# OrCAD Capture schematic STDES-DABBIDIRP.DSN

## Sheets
1 AUX_SECTION: size B
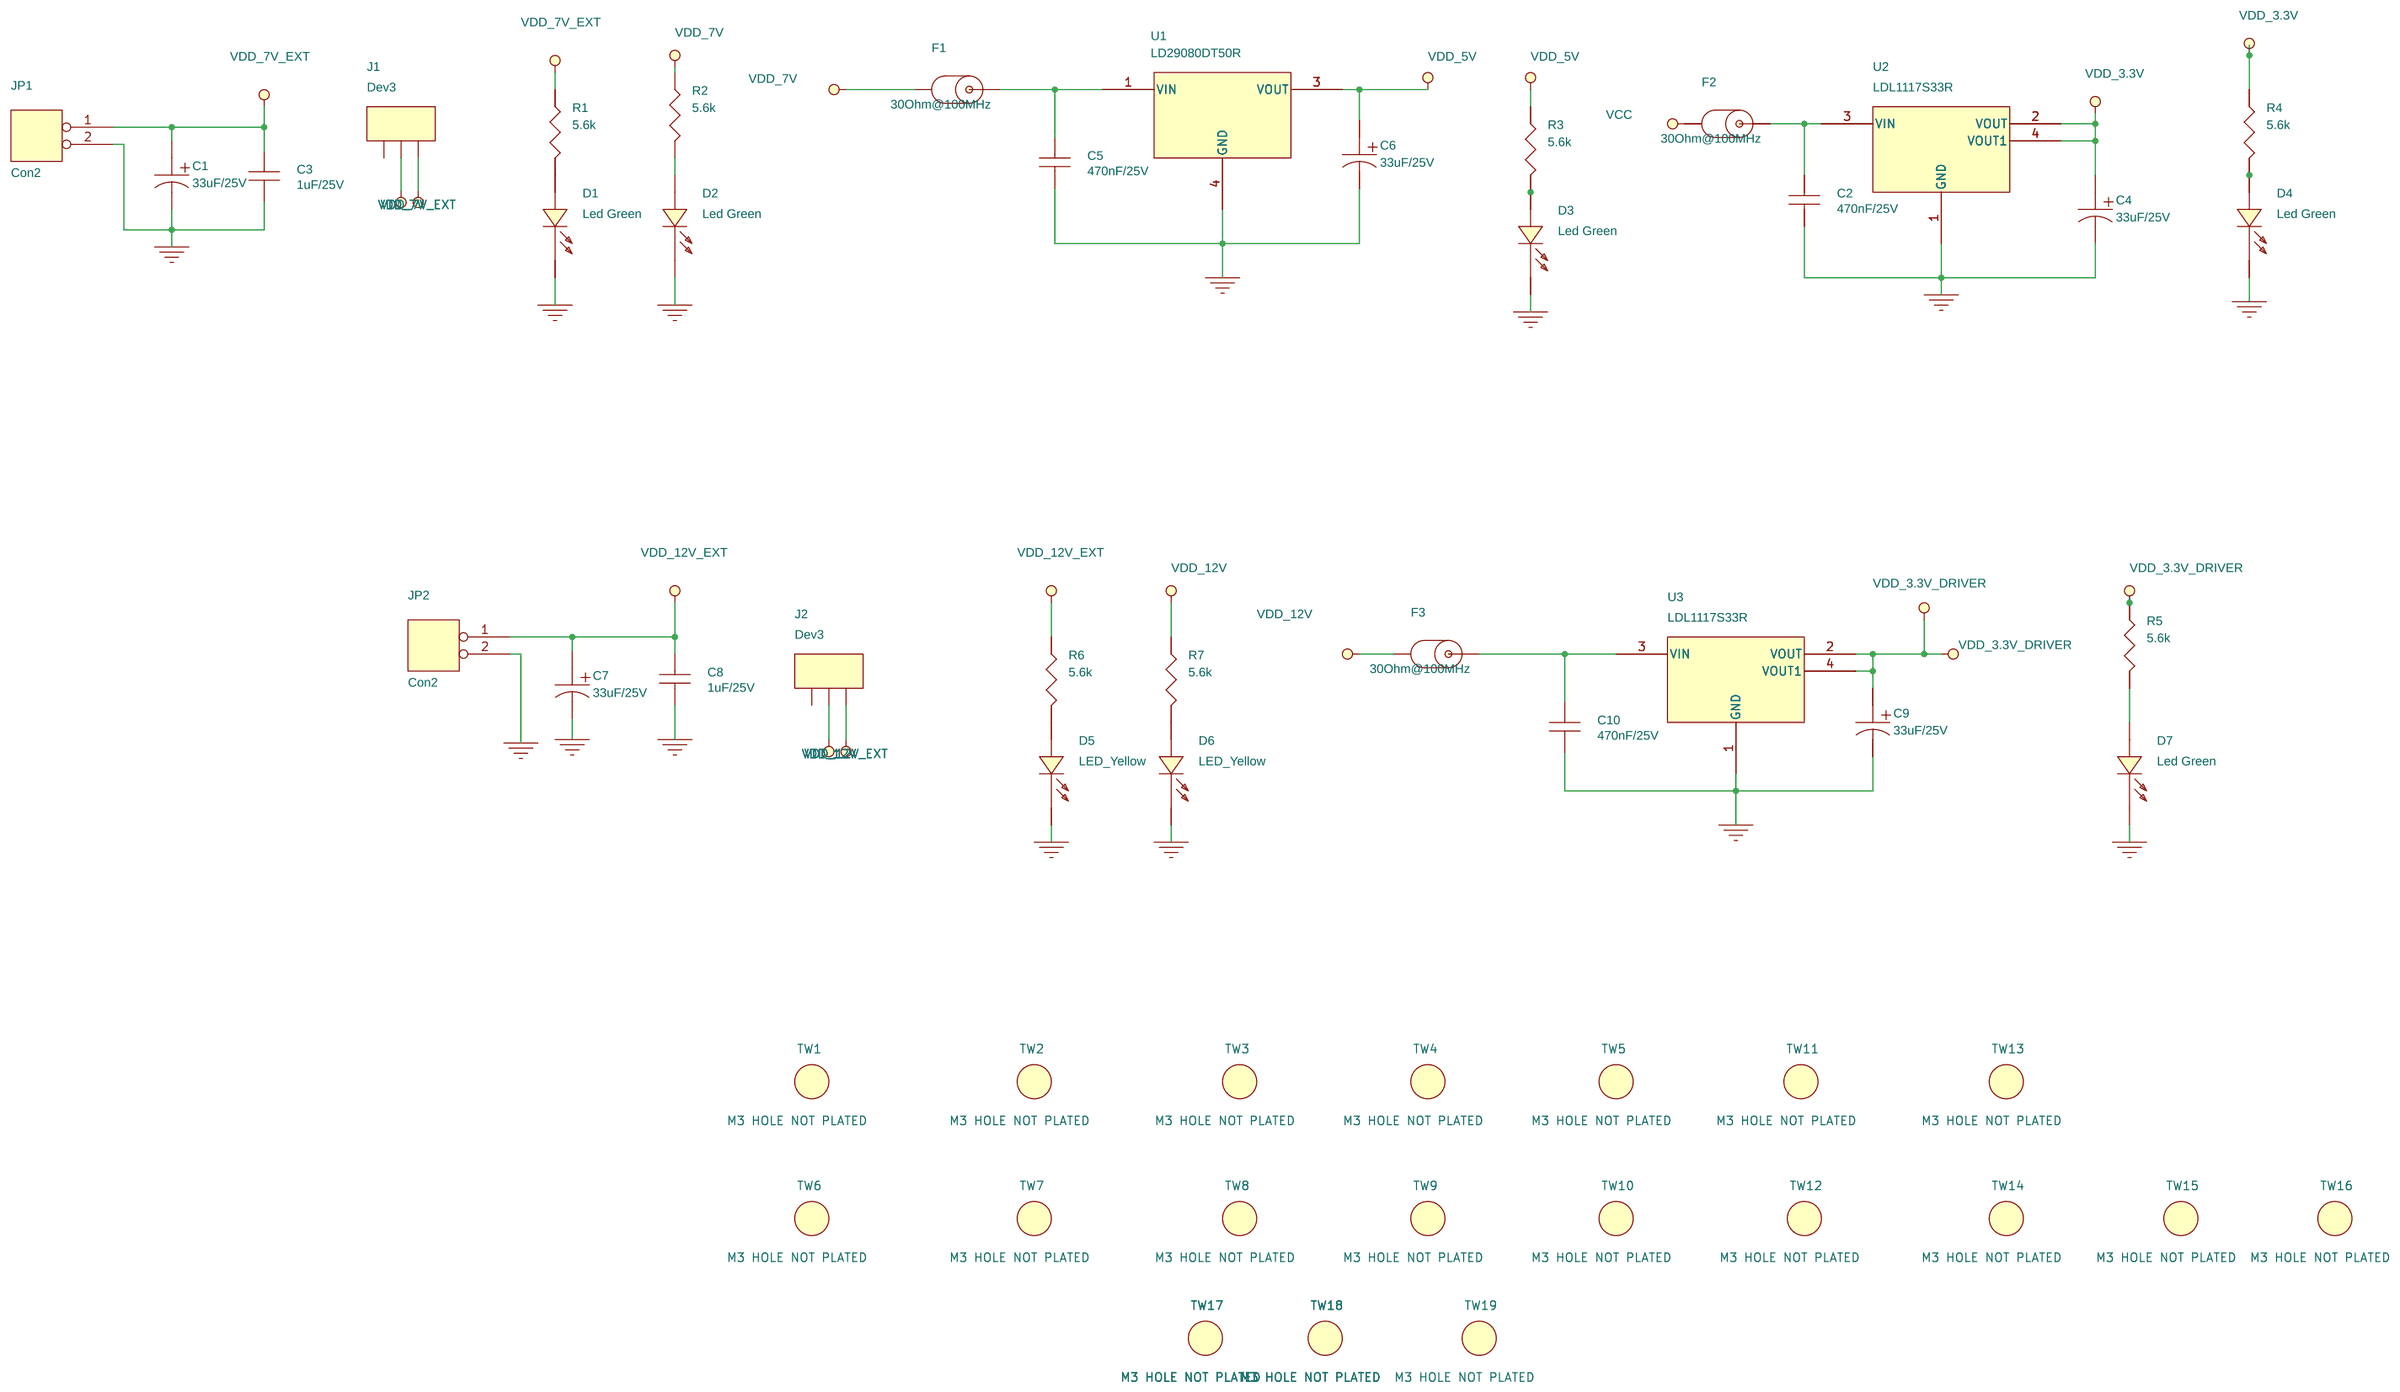
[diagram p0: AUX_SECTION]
2 TEMP_SECTION: size C
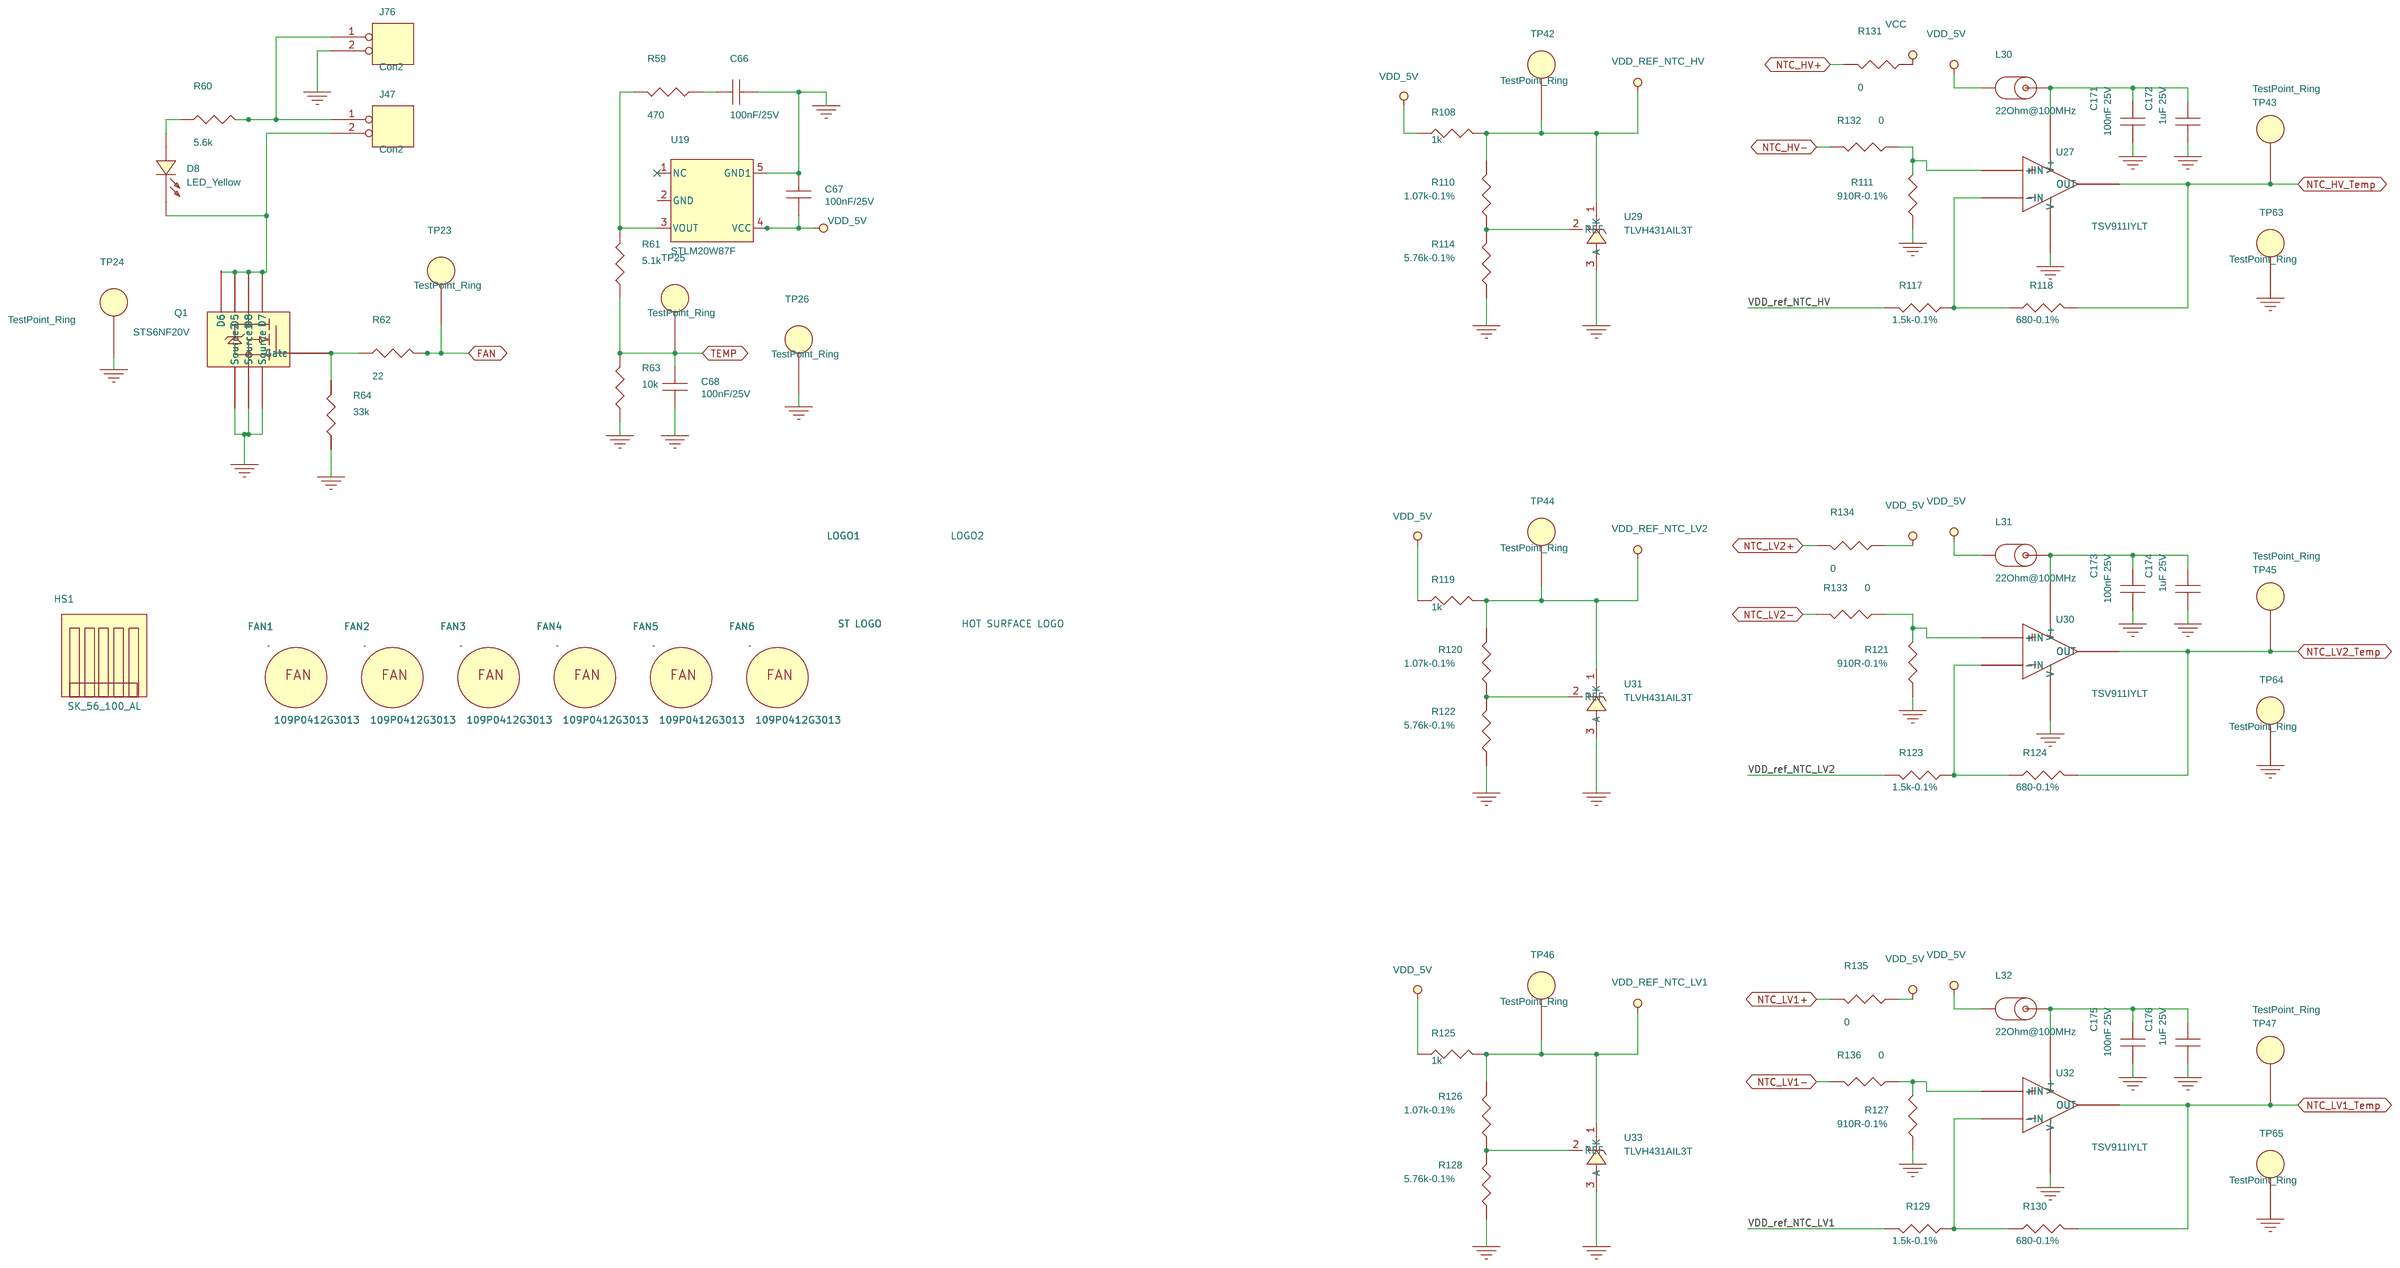
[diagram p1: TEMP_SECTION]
3 SENSE_SECTION: size D
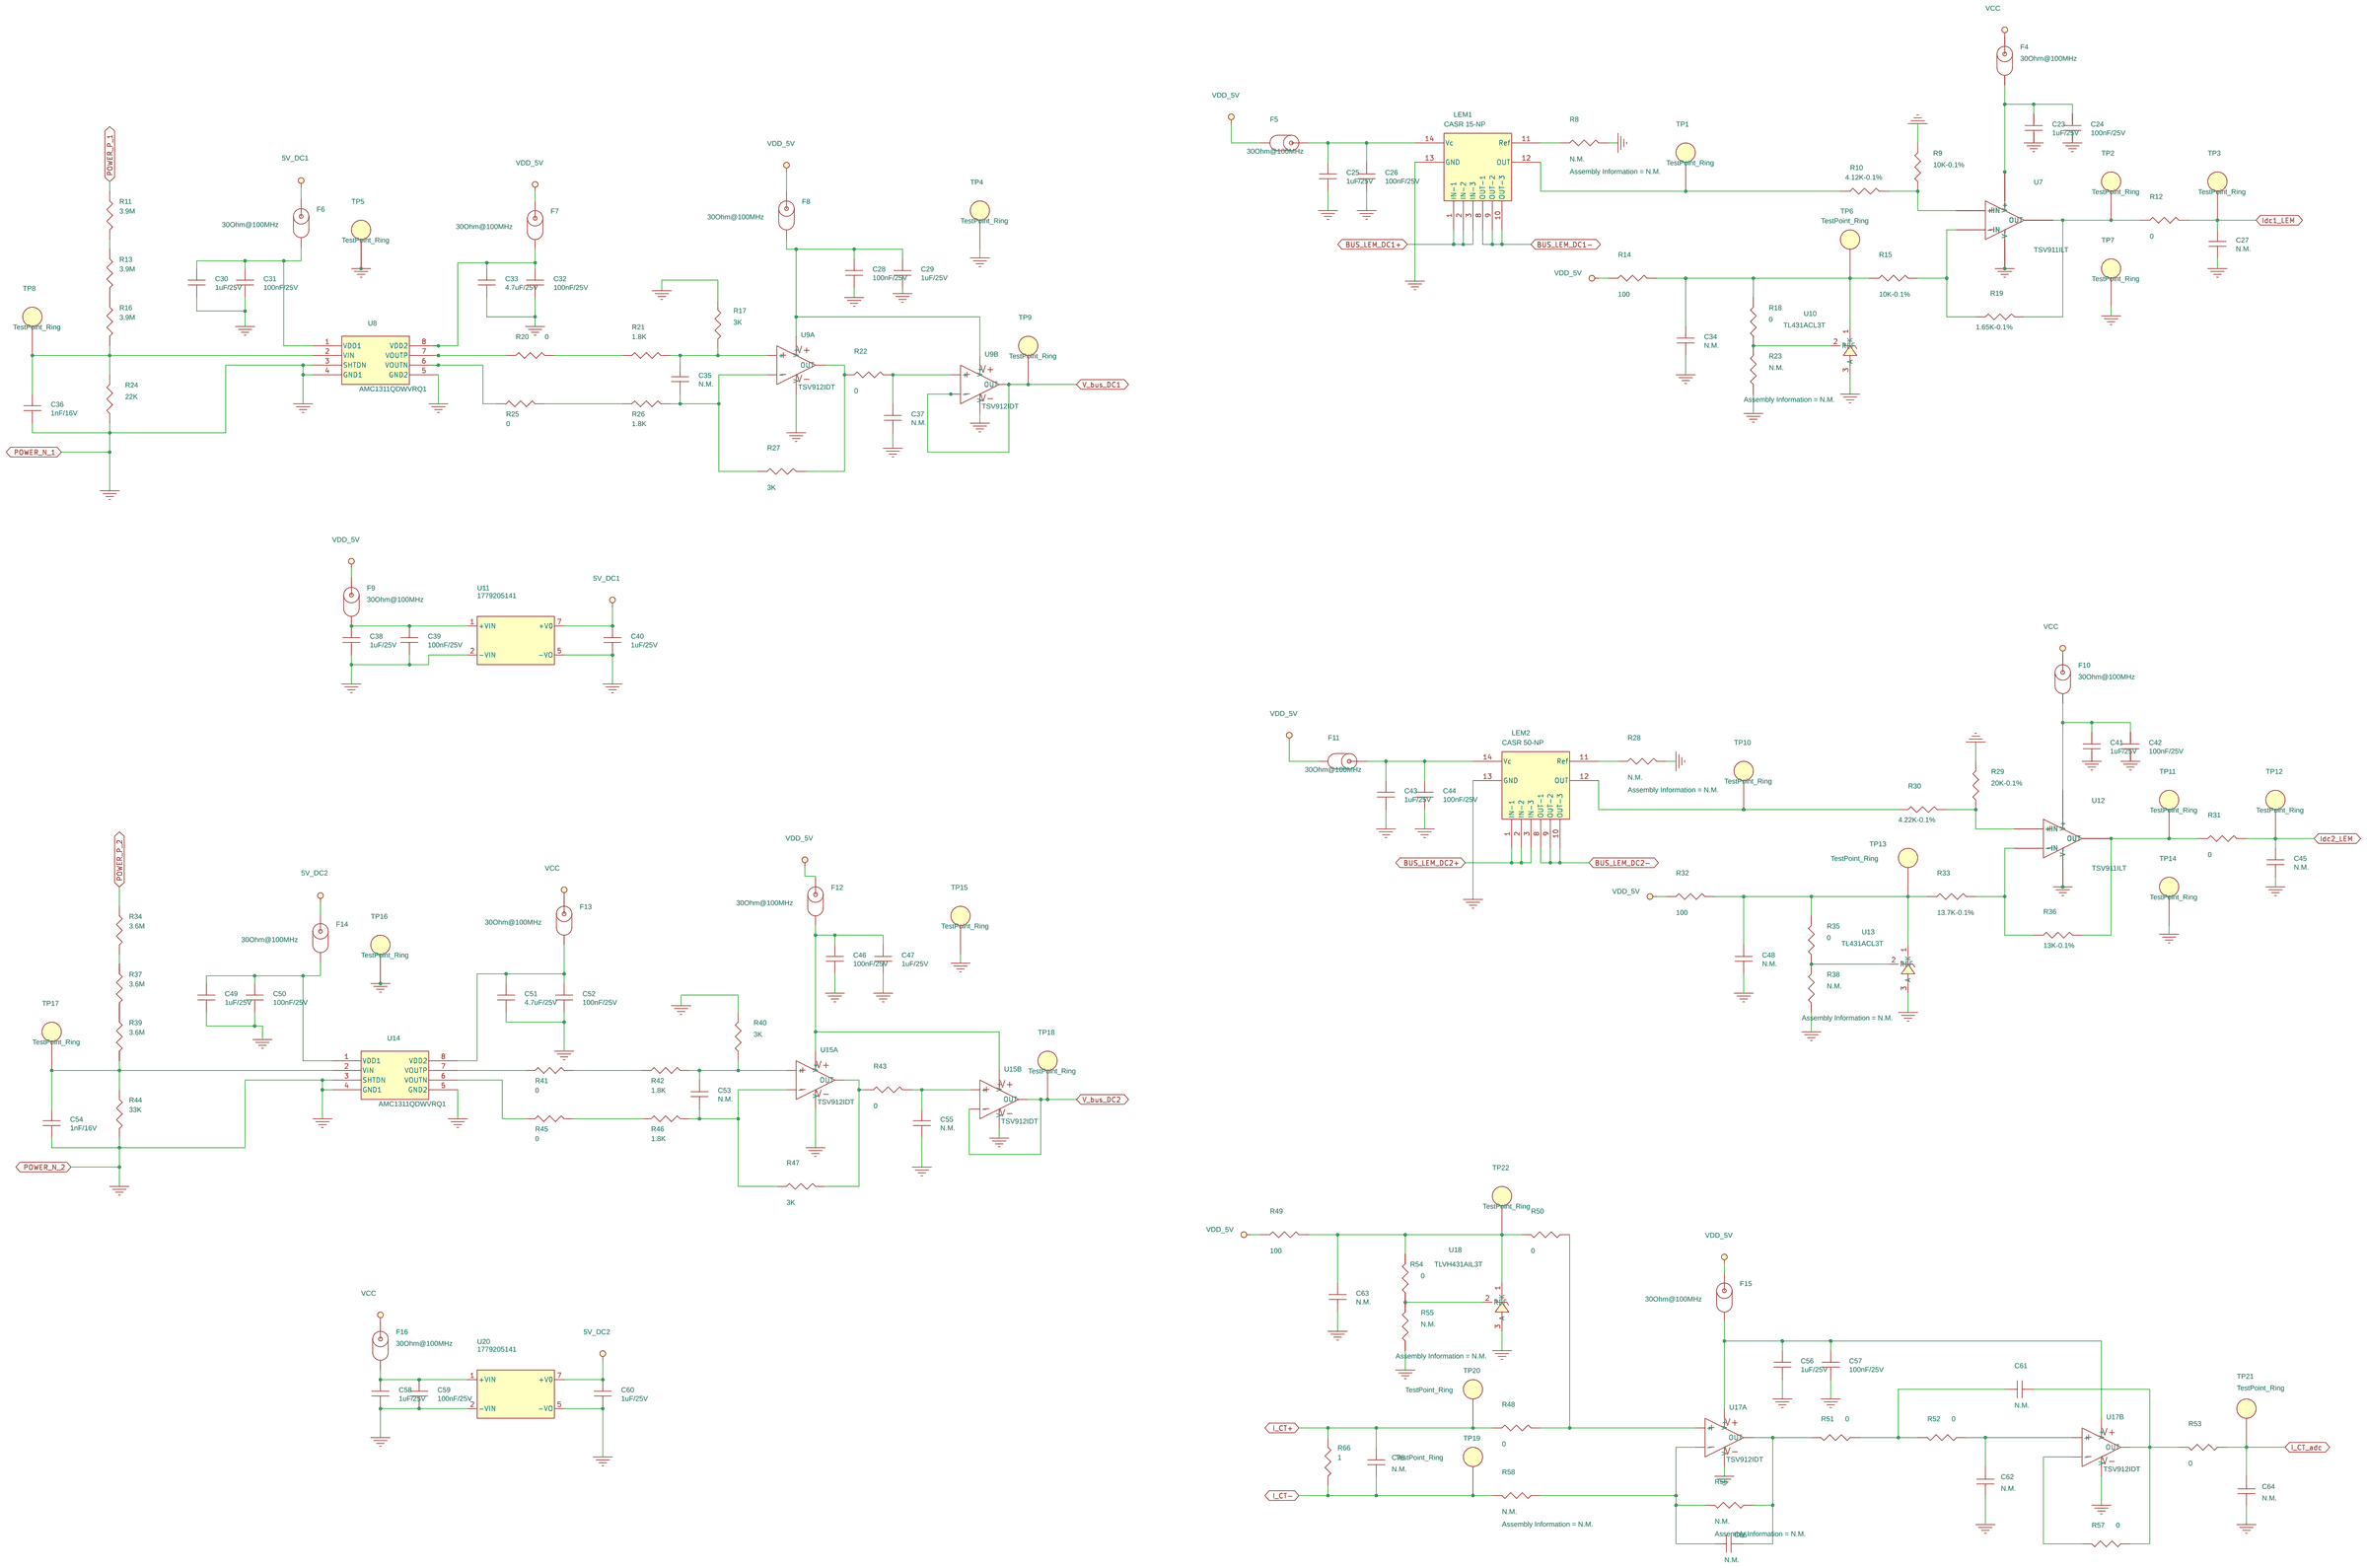
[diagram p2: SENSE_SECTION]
4 CONNECTOR: size B
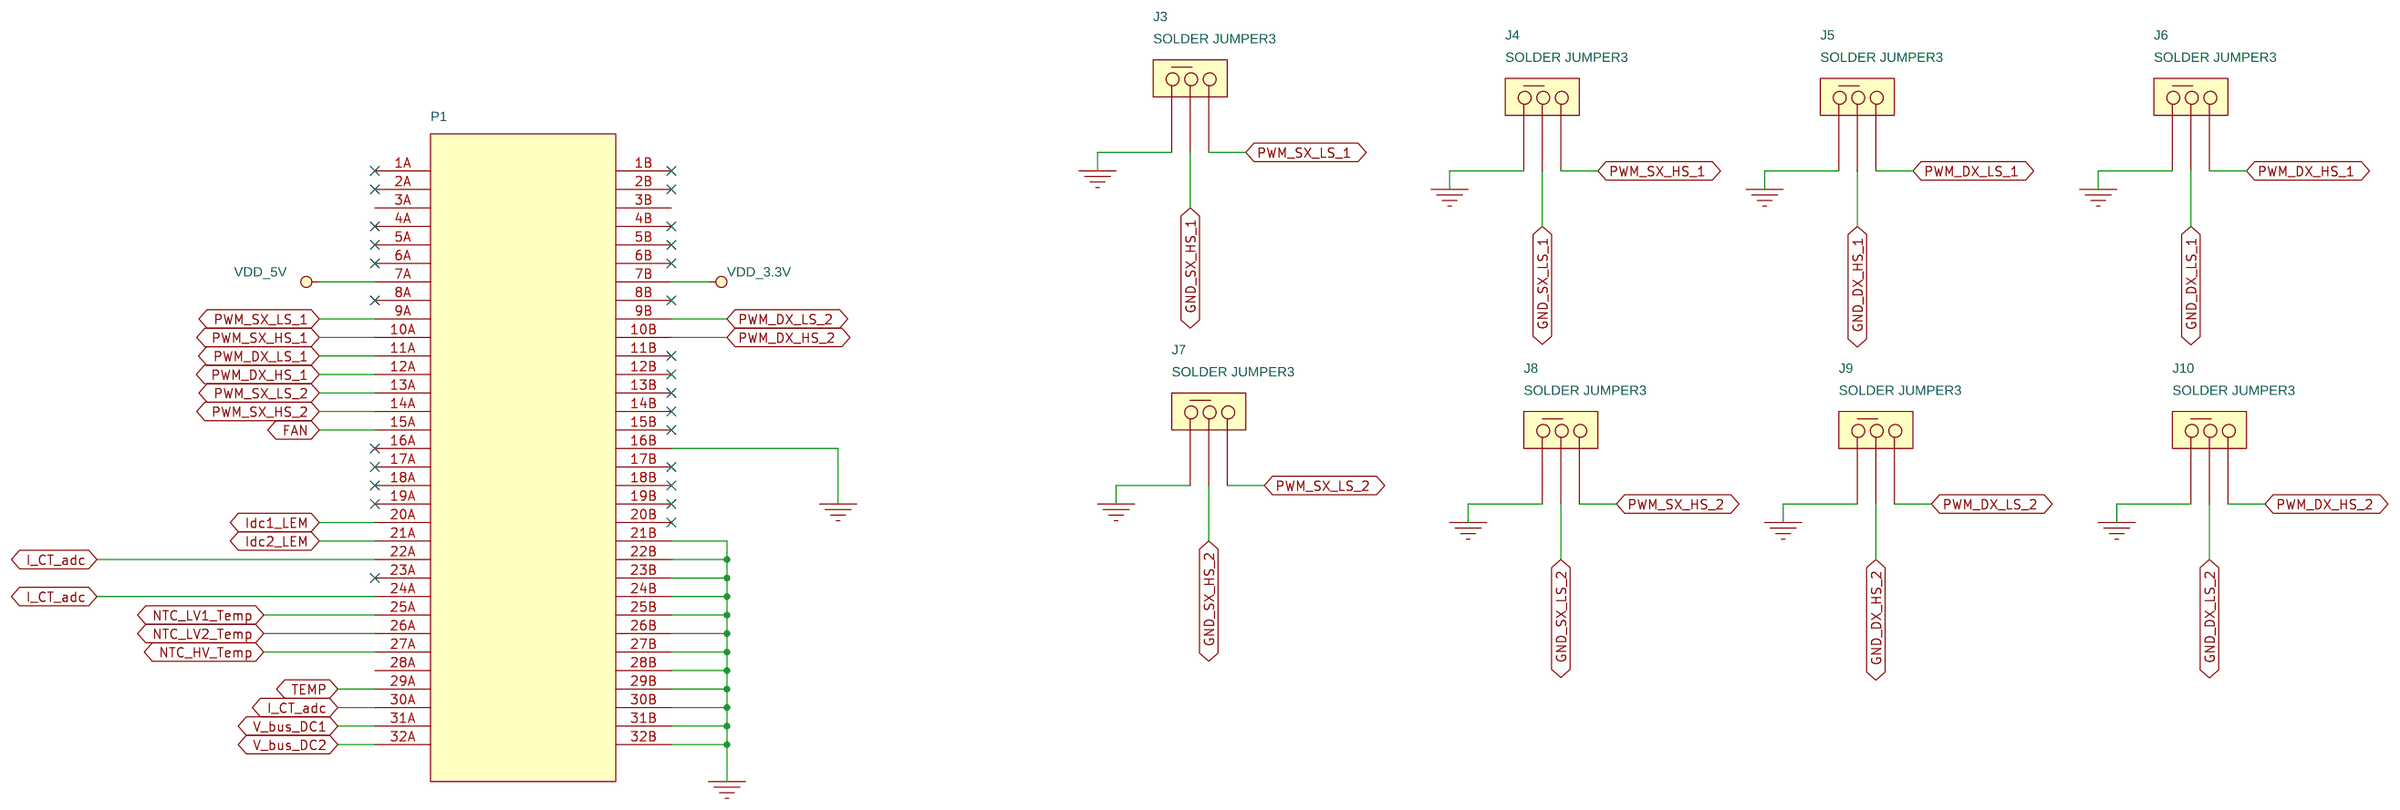
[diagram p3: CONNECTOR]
5 DRIVER_SECTION: size A
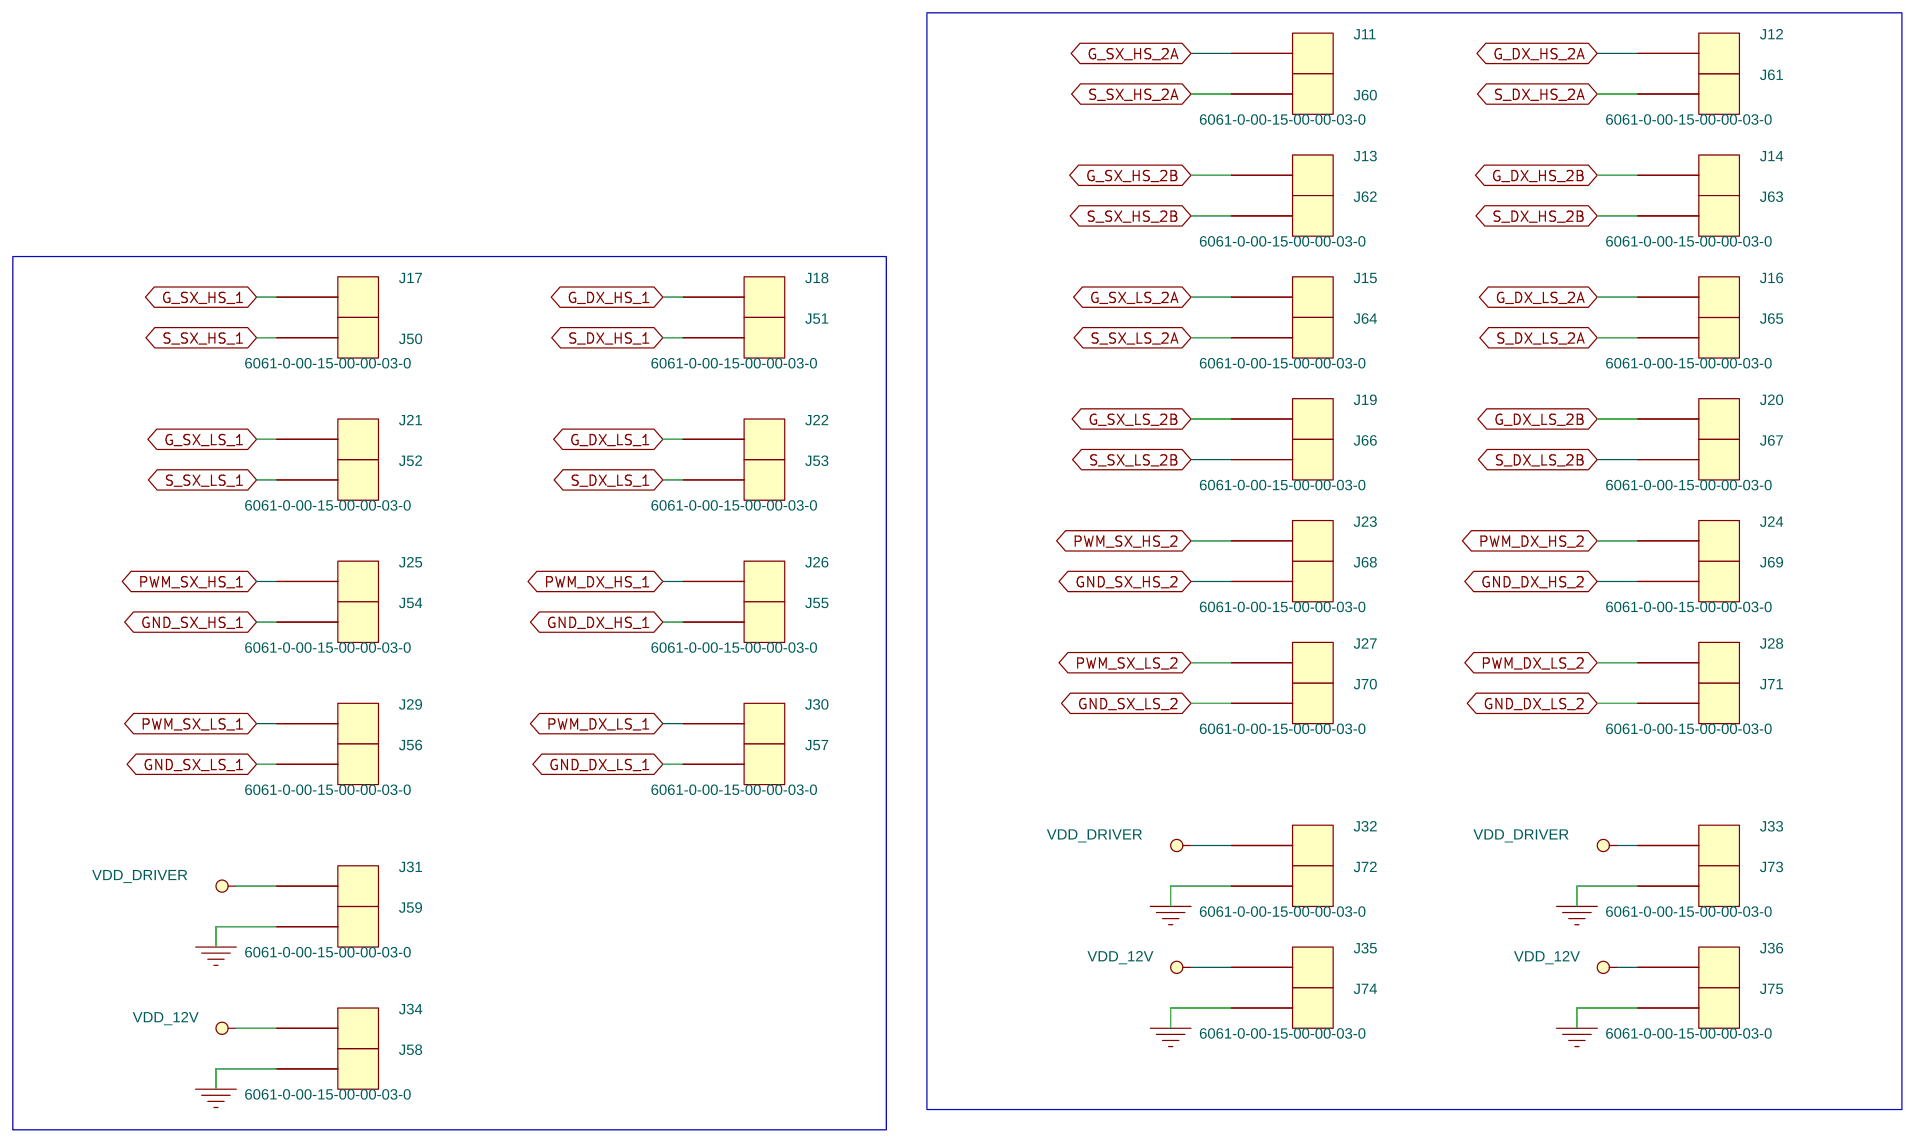
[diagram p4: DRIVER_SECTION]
6 POWER_SECTION: size C
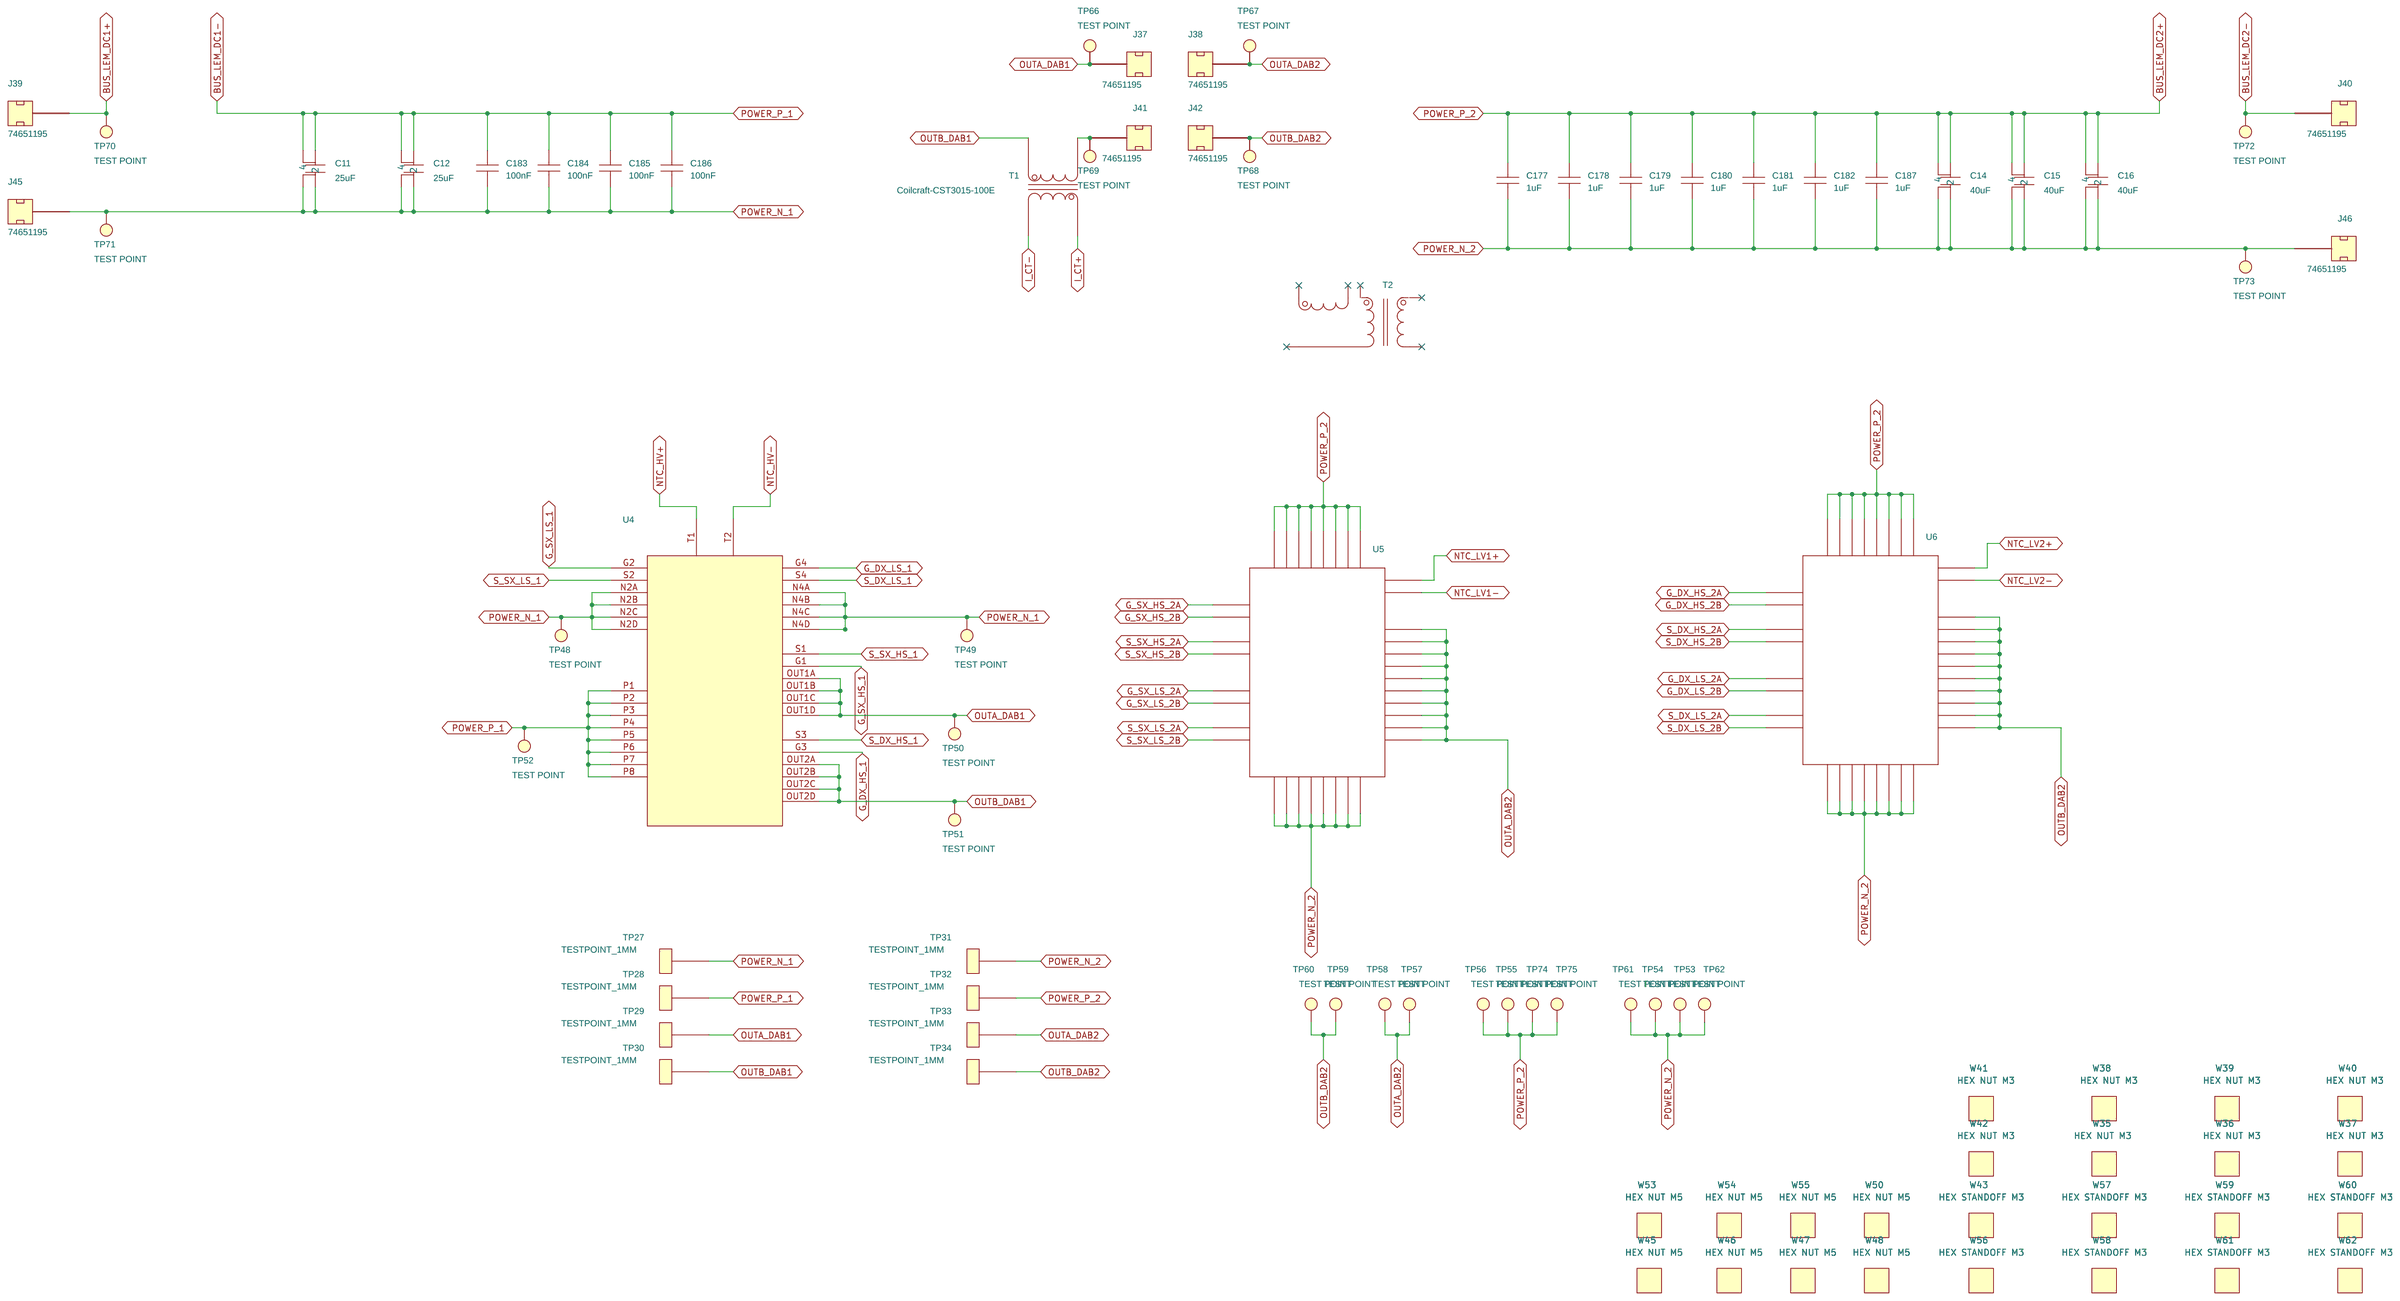
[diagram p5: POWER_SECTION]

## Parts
sheet AUX_SECTION
C1  33uF/25V  [6P6x6P6]
C2  470nF/25V  [C_0603]
C3  1uF/25V  [C_0603]
C4  33uF/25V  [6P6x6P6]
C5  470nF/25V  [C_0603]
C6  33uF/25V  [6P6x6P6]
C7  33uF/25V  [6P6x6P6]
C8  1uF/25V  [C_0603]
C9  33uF/25V  [6P6x6P6]
C10  470nF/25V  [C_0603]
D1  Led Green  [ledc200x125x80l50_55n]
D2  Led Green  [ledc200x125x80l50_55n]
D3  Led Green  [ledc200x125x80l50_55n]
D4  Led Green  [ledc200x125x80l50_55n]
D5  LED_Yellow  [ledc200x125x80l50_55n]
D6  LED_Yellow  [ledc200x125x80l50_55n]
D7  Led Green  [ledc200x125x80l50_55n]
F1  30Ohm@100MHz  [L_0805]
F2  30Ohm@100MHz  [L_0805]
F3  30Ohm@100MHz  [L_0805]
J1  Dev3  [SWITCH_3P]
J2  Dev3  [SWITCH_3P]
JP1  Con2  [Mor2x508]
JP2  Con2  [Mor2x508]
R1  5.6k  [r_1206]
R2  5.6k  [r_1206]
R3  5.6k  [r_1206]
R4  5.6k  [r_1206]
R5  5.6k  [r_1206]
R6  5.6k  [r_1206]
R7  5.6k  [r_1206]
TW1  M3 HOLE NOT PLATED  [vite-m3-noplated]
TW2  M3 HOLE NOT PLATED  [vite-m3-noplated]
TW3  M3 HOLE NOT PLATED  [vite-m3-noplated]
TW4  M3 HOLE NOT PLATED  [vite-m3-noplated]
TW5  M3 HOLE NOT PLATED  [vite-m3-noplated]
TW6  M3 HOLE NOT PLATED  [vite-m3-noplated]
TW7  M3 HOLE NOT PLATED  [vite-m3-noplated]
TW8  M3 HOLE NOT PLATED  [vite-m3-noplated]
TW9  M3 HOLE NOT PLATED  [vite-m3-noplated]
TW10  M3 HOLE NOT PLATED  [vite-m3-noplated]
TW11  M3 HOLE NOT PLATED  [vite-m3-noplated]
TW12  M3 HOLE NOT PLATED  [vite-m3-noplated]
TW13  M3 HOLE NOT PLATED  [vite-m3-noplated]
TW14  M3 HOLE NOT PLATED  [vite-m3-noplated]
TW15  M3 HOLE NOT PLATED  [vite-m3-noplated]
TW16  M3 HOLE NOT PLATED  [vite-m3-noplated]
TW17  M3 HOLE NOT PLATED  [vite-m3-noplated]
TW18  M3 HOLE NOT PLATED  [vite-m3-noplated]
TW19  M3 HOLE NOT PLATED  [vite-m3-noplated]
U1  LD29080DT50R  [dpak4p228_972x240l120x77t520]
U2  LDL1117S33R  [sot223-4p230_700x190l65x72]
U3  LDL1117S33R  [sot223-4p230_700x190l65x72]
sheet CONNECTOR
J3  SOLDER JUMPER3  [jumper_0603_3pin_drop]
J4  SOLDER JUMPER3  [jumper_0603_3pin_drop]
J5  SOLDER JUMPER3  [jumper_0603_3pin_drop]
J6  SOLDER JUMPER3  [jumper_0603_3pin_drop]
J7  SOLDER JUMPER3  [jumper_0603_3pin_drop]
J8  SOLDER JUMPER3  [jumper_0603_3pin_drop]
J9  SOLDER JUMPER3  [jumper_0603_3pin_drop]
J10  SOLDER JUMPER3  [jumper_0603_3pin_drop]
P1  CON64AB  [connERNI_284166_Female32X2]
sheet DRIVER_SECTION
J11  6061-0-00-15-00-00-03-0  [6061-0-00-15-00-00-03-0]
J12  6061-0-00-15-00-00-03-0  [6061-0-00-15-00-00-03-0]
J13  6061-0-00-15-00-00-03-0  [6061-0-00-15-00-00-03-0]
J14  6061-0-00-15-00-00-03-0  [6061-0-00-15-00-00-03-0]
J15  6061-0-00-15-00-00-03-0  [6061-0-00-15-00-00-03-0]
J16  6061-0-00-15-00-00-03-0  [6061-0-00-15-00-00-03-0]
J17  6061-0-00-15-00-00-03-0  [6061-0-00-15-00-00-03-0]
J18  6061-0-00-15-00-00-03-0  [6061-0-00-15-00-00-03-0]
J19  6061-0-00-15-00-00-03-0  [6061-0-00-15-00-00-03-0]
J20  6061-0-00-15-00-00-03-0  [6061-0-00-15-00-00-03-0]
J21  6061-0-00-15-00-00-03-0  [6061-0-00-15-00-00-03-0]
J22  6061-0-00-15-00-00-03-0  [6061-0-00-15-00-00-03-0]
J23  6061-0-00-15-00-00-03-0  [6061-0-00-15-00-00-03-0]
J24  6061-0-00-15-00-00-03-0  [6061-0-00-15-00-00-03-0]
J25  6061-0-00-15-00-00-03-0  [6061-0-00-15-00-00-03-0]
J26  6061-0-00-15-00-00-03-0  [6061-0-00-15-00-00-03-0]
J27  6061-0-00-15-00-00-03-0  [6061-0-00-15-00-00-03-0]
J28  6061-0-00-15-00-00-03-0  [6061-0-00-15-00-00-03-0]
J29  6061-0-00-15-00-00-03-0  [6061-0-00-15-00-00-03-0]
J30  6061-0-00-15-00-00-03-0  [6061-0-00-15-00-00-03-0]
J31  6061-0-00-15-00-00-03-0  [6061-0-00-15-00-00-03-0]
J32  6061-0-00-15-00-00-03-0  [6061-0-00-15-00-00-03-0]
J33  6061-0-00-15-00-00-03-0  [6061-0-00-15-00-00-03-0]
J34  6061-0-00-15-00-00-03-0  [6061-0-00-15-00-00-03-0]
J35  6061-0-00-15-00-00-03-0  [6061-0-00-15-00-00-03-0]
J36  6061-0-00-15-00-00-03-0  [6061-0-00-15-00-00-03-0]
J50  6061-0-00-15-00-00-03-0  [6061-0-00-15-00-00-03-0]
J51  6061-0-00-15-00-00-03-0  [6061-0-00-15-00-00-03-0]
J52  6061-0-00-15-00-00-03-0  [6061-0-00-15-00-00-03-0]
J53  6061-0-00-15-00-00-03-0  [6061-0-00-15-00-00-03-0]
J54  6061-0-00-15-00-00-03-0  [6061-0-00-15-00-00-03-0]
J55  6061-0-00-15-00-00-03-0  [6061-0-00-15-00-00-03-0]
J56  6061-0-00-15-00-00-03-0  [6061-0-00-15-00-00-03-0]
J57  6061-0-00-15-00-00-03-0  [6061-0-00-15-00-00-03-0]
J58  6061-0-00-15-00-00-03-0  [6061-0-00-15-00-00-03-0]
J59  6061-0-00-15-00-00-03-0  [6061-0-00-15-00-00-03-0]
J60  6061-0-00-15-00-00-03-0  [6061-0-00-15-00-00-03-0]
J61  6061-0-00-15-00-00-03-0  [6061-0-00-15-00-00-03-0]
J62  6061-0-00-15-00-00-03-0  [6061-0-00-15-00-00-03-0]
J63  6061-0-00-15-00-00-03-0  [6061-0-00-15-00-00-03-0]
J64  6061-0-00-15-00-00-03-0  [6061-0-00-15-00-00-03-0]
J65  6061-0-00-15-00-00-03-0  [6061-0-00-15-00-00-03-0]
J66  6061-0-00-15-00-00-03-0  [6061-0-00-15-00-00-03-0]
J67  6061-0-00-15-00-00-03-0  [6061-0-00-15-00-00-03-0]
J68  6061-0-00-15-00-00-03-0  [6061-0-00-15-00-00-03-0]
J69  6061-0-00-15-00-00-03-0  [6061-0-00-15-00-00-03-0]
J70  6061-0-00-15-00-00-03-0  [6061-0-00-15-00-00-03-0]
J71  6061-0-00-15-00-00-03-0  [6061-0-00-15-00-00-03-0]
J72  6061-0-00-15-00-00-03-0  [6061-0-00-15-00-00-03-0]
J73  6061-0-00-15-00-00-03-0  [6061-0-00-15-00-00-03-0]
J74  6061-0-00-15-00-00-03-0  [6061-0-00-15-00-00-03-0]
J75  6061-0-00-15-00-00-03-0  [6061-0-00-15-00-00-03-0]
sheet POWER_SECTION
C11  25uF  [WCAP-FTDB_42x45x60_cs]
C12  25uF  [WCAP-FTDB_42x45x60_cs]
C14  40uF  [WCAP-FTDB_42x30x45_cs]
C15  40uF  [WCAP-FTDB_42x30x45_cs]
C16  40uF  [WCAP-FTDB_42x30x45_cs]
C177  1uF  [C_2220]
C178  1uF  [C_2220]
C179  1uF  [C_2220]
C180  1uF  [C_2220]
C181  1uF  [C_2220]
C182  1uF  [C_2220]
C183  100nF  [C_2220]
C184  100nF  [C_2220]
C185  100nF  [C_2220]
C186  100nF  [C_2220]
C187  1uF  [C_2220]
J37  74651195  [wurth_74651195]
J38  74651195  [wurth_74651195]
J39  74651195  [wurth_74651195]
J40  74651195  [wurth_74651195]
J41  74651195  [wurth_74651195]
J42  74651195  [wurth_74651195]
J45  74651195  [wurth_74651195]
J46  74651195  [wurth_74651195]
T1  Coilcraft-CST3015-100E  [transf_Coilcraft-CST3015]
T2  Frenetic_32011-04  [Frenetic_32011-04_temp]
TP27  TESTPOINT_1MM  [TESTPOINT_1MM_SMD]
TP28  TESTPOINT_1MM  [TESTPOINT_1MM_SMD]
TP29  TESTPOINT_1MM  [TESTPOINT_1MM_SMD]
TP30  TESTPOINT_1MM  [TESTPOINT_1MM_SMD]
TP31  TESTPOINT_1MM  [TESTPOINT_1MM_SMD]
TP32  TESTPOINT_1MM  [TESTPOINT_1MM_SMD]
TP33  TESTPOINT_1MM  [TESTPOINT_1MM_SMD]
TP34  TESTPOINT_1MM  [TESTPOINT_1MM_SMD]
TP48  TEST POINT  [harwin_s1751-46r]
TP49  TEST POINT  [harwin_s1751-46r]
TP50  TEST POINT  [harwin_s1751-46r]
TP51  TEST POINT  [harwin_s1751-46r]
TP52  TEST POINT  [harwin_s1751-46r]
TP53  TEST POINT  [harwin_s1751-46r]
TP54  TEST POINT  [harwin_s1751-46r]
TP55  TEST POINT  [harwin_s1751-46r]
TP56  TEST POINT  [harwin_s1751-46r]
TP57  TEST POINT  [harwin_s1751-46r]
TP58  TEST POINT  [harwin_s1751-46r]
TP59  TEST POINT  [harwin_s1751-46r]
TP60  TEST POINT  [harwin_s1751-46r]
TP61  TEST POINT  [harwin_s1751-46r]
TP62  TEST POINT  [harwin_s1751-46r]
TP66  TEST POINT  [harwin_s1751-46r]
TP67  TEST POINT  [harwin_s1751-46r]
TP68  TEST POINT  [harwin_s1751-46r]
TP69  TEST POINT  [harwin_s1751-46r]
TP70  TEST POINT  [harwin_s1751-46r]
TP71  TEST POINT  [harwin_s1751-46r]
TP72  TEST POINT  [harwin_s1751-46r]
TP73  TEST POINT  [harwin_s1751-46r]
TP74  TEST POINT  [harwin_s1751-46r]
TP75  TEST POINT  [harwin_s1751-46r]
U4  A2F12M12W2-F1  [A2F12M12W2-F1]
U5  A2H6M12W3  [A2H6M12W3]
U6  A2H6M12W3  [A2H6M12W3]
W35  HEX NUT M3
W36  HEX NUT M3
W37  HEX NUT M3
W38  HEX NUT M3
W39  HEX NUT M3
W40  HEX NUT M3
W41  HEX NUT M3
W42  HEX NUT M3
W43  HEX STANDOFF M3
W45  HEX NUT M5
W46  HEX NUT M5
W47  HEX NUT M5
W48  HEX NUT M5
W50  HEX NUT M5
W53  HEX NUT M5
W54  HEX NUT M5
W55  HEX NUT M5
W56  HEX STANDOFF M3
W57  HEX STANDOFF M3
W58  HEX STANDOFF M3
W59  HEX STANDOFF M3
W60  HEX STANDOFF M3
W61  HEX STANDOFF M3
W62  HEX STANDOFF M3
sheet SENSE_SECTION
C23  1uF/25V  [C_0603]
C24  100nF/25V  [C_0603]
C25  1uF/25V  [C_0603]
C26  100nF/25V  [C_0603]
C27  N.M.  [C_0603]
C28  100nF/25V  [C_0603]
C29  1uF/25V  [C_0603]
C30  1uF/25V  [C_0603]
C31  100nF/25V  [C_0603]
C32  100nF/25V  [C_0603]
C33  4.7uF/25V  [C_0603]
C34  N.M.  [C_0603]
C35  N.M.  [C_0603]
C36  1nF/16V  [C_0603]
C37  N.M.  [C_0603]
C38  1uF/25V  [C_0603]
C39  100nF/25V  [C_0603]
C40  1uF/25V  [C_0603]
C41  1uF/25V  [C_0603]
C42  100nF/25V  [C_0603]
C43  1uF/25V  [C_0603]
C44  100nF/25V  [C_0603]
C45  N.M.  [C_0603]
C46  100nF/25V  [C_0603]
C47  1uF/25V  [C_0603]
C48  N.M.  [C_0603]
C49  1uF/25V  [C_0603]
C50  100nF/25V  [C_0603]
C51  4.7uF/25V  [C_0603]
C52  100nF/25V  [C_0603]
C53  N.M.  [C_0603]
C54  1nF/16V  [C_0603]
C55  N.M.  [C_0603]
C56  1uF/25V  [C_0603]
C57  100nF/25V  [C_0603]
C58  1uF/25V  [C_0603]
C59  100nF/25V  [C_0603]
C60  1uF/25V  [C_0603]
C61  N.M.  [C_0603]
C62  N.M.  [C_0603]
C63  N.M.  [C_0603]
C64  N.M.  [C_0603]
C65  N.M.  [C_0603]
C76  N.M.  [C_0603]
F4  30Ohm@100MHz  [L_0805]
F5  30Ohm@100MHz  [L_0805]
F6  30Ohm@100MHz  [L_0805]
F7  30Ohm@100MHz  [L_0805]
F8  30Ohm@100MHz  [L_0805]
F9  30Ohm@100MHz  [L_0805]
F10  30Ohm@100MHz  [L_0805]
F11  30Ohm@100MHz  [L_0805]
F12  30Ohm@100MHz  [L_0805]
F13  30Ohm@100MHz  [L_0805]
F14  30Ohm@100MHz  [L_0805]
F15  30Ohm@100MHz  [L_0805]
F16  30Ohm@100MHz  [L_0805]
LEM1  CASR 15-NP  [CASR15-NP]
LEM2  CASR 50-NP  [CASR15-NP]
R8  N.M.  [r_0603]
R9  10K-0.1%  [r_0603]
R10  4.12K-0.1%  [r_0603]
R11  3.9M  [r_1206]
R12  0  [r_0603]
R13  3.9M  [r_1206]
R14  100  [r_0603]
R15  10K-0.1%  [r_0603]
R16  3.9M  [r_1206]
R17  3K  [r_0603]
R18  0  [r_0603]
R19  1.65K-0.1%  [r_0603]
R20  0  [r_0603]
R21  1.8K  [r_0603]
R22  0  [r_0603]
R23  N.M.  [r_0603]
R24  22K  [r_0603]
R25  0  [r_0603]
R26  1.8K  [r_0603]
R27  3K  [r_0603]
R28  N.M.  [r_0603]
R29  20K-0.1%  [r_0603]
R30  4.22K-0.1%  [r_0603]
R31  0  [r_0603]
R32  100  [r_0603]
R33  13.7K-0.1%  [r_0603]
R34  3.6M  [r_1206]
R35  0  [r_0603]
R36  13K-0.1%  [r_0603]
R37  3.6M  [r_1206]
R38  N.M.  [r_0603]
R39  3.6M  [r_1206]
R40  3K  [r_0603]
R41  0  [r_0603]
R42  1.8K  [r_0603]
R43  0  [r_0603]
R44  33K  [r_0603]
R45  0  [r_0603]
R46  1.8K  [r_0603]
R47  3K  [r_0603]
R48  0  [r_0603]
R49  100  [r_0603]
R50  0  [r_0603]
R51  0  [r_0603]
R52  0  [r_0603]
R53  0  [r_0603]
R54  0  [r_0603]
R55  N.M.  [r_0603]
R56  N.M.  [r_0603]
R57  0  [r_0603]
R58  N.M.  [r_0603]
R66  1  [r_2512]
TP1  TestPoint_Ring  [TestPointD100]
TP2  TestPoint_Ring  [TestPointD100]
TP3  TestPoint_Ring  [TestPointD100]
TP4  TestPoint_Ring  [TestPointD100]
TP5  TestPoint_Ring  [TestPointD100]
TP6  TestPoint_Ring  [TestPointD100]
TP7  TestPoint_Ring  [TestPointD100]
TP8  TestPoint_Ring  [TestPointD100]
TP9  TestPoint_Ring  [TestPointD100]
TP10  TestPoint_Ring  [TestPointD100]
TP11  TestPoint_Ring  [TestPointD100]
TP12  TestPoint_Ring  [TestPointD100]
TP13  TestPoint_Ring  [TestPointD100]
TP14  TestPoint_Ring  [TestPointD100]
TP15  TestPoint_Ring  [TestPointD100]
TP16  TestPoint_Ring  [TestPointD100]
TP17  TestPoint_Ring  [TestPointD100]
TP18  TestPoint_Ring  [TestPointD100]
TP19  TestPoint_Ring  [TestPointD100]
TP20  TestPoint_Ring  [TestPointD100]
TP21  TestPoint_Ring  [TestPointD100]
TP22  TestPoint_Ring  [TestPointD100]
U7  TSV911ILT  [sot23-5p95_280x145l45x40n]
U8  AMC1311QDWVRQ1  [soic8p127_585x1150x331l75x38n]
U9  TSV912IDT  [SOIC8P127_490X600X175L83X42N]  (sections A,B)
U10  TL431ACL3T  [SOT23-3P97_255x140l40x40n]
U11  1779205141  [1779205141]
U12  TSV911ILT  [sot23-5p95_280x145l45x40n]
U13  TL431ACL3T  [SOT23-3P97_255x140l40x40n]
U14  AMC1311QDWVRQ1  [soic8p127_585x1150x331l75x38n]
U15  TSV912IDT  [SOIC8P127_490X600X175L83X42N]  (sections A,B)
U17  TSV912IDT  [SOIC8P127_490X600X175L83X42N]  (sections A,B)
U18  TLVH431AIL3T  [SOT23-3P97_255x140l40x40n]
U20  1779205141  [1779205141]
sheet TEMP_SECTION
C66  100nF/25V  [C_0603]
C67  100nF/25V  [C_0603]
C68  100nF/25V  [C_0603]
C171  100nF 25V  [C_0603]
C172  1uF 25V  [C_0603]
C173  100nF 25V  [C_0603]
C174  1uF 25V  [C_0603]
C175  100nF 25V  [C_0603]
C176  1uF 25V  [C_0603]
D8  LED_Yellow  [ledc200x125x80l50_55n]
FAN1  109P0412G3013  [109P0412G3013]
FAN2  109P0412G3013  [109P0412G3013]
FAN3  109P0412G3013  [109P0412G3013]
FAN4  109P0412G3013  [109P0412G3013]
FAN5  109P0412G3013  [109P0412G3013]
FAN6  109P0412G3013  [109P0412G3013]
HS1  SK_56_100_AL  [SK_56_100_AL]
J47  Con2  [Mor2x508]
J76  Con2  [Mor2x508]
L30  22Ohm@100MHz  [r_0805]
L31  22Ohm@100MHz  [r_0805]
L32  22Ohm@100MHz  [r_0805]
LOGO1  ST LOGO  [STLogo12mm]
LOGO2  HOT SURFACE LOGO  [Hot-Surface-Logo8mm]
Q1  STS6NF20V  [SOIC8P127_490X600X175L83X42N]
R59  470  [r_0603]
R60  5.6k  [r_0603]
R61  5.1k  [r_0603]
R62  22  [r_0603]
R63  10k  [r_0603]
R64  33k  [r_0603]
R108  1k  [r_0603]
R110  1.07k-0.1%  [r_0603]
R111  910R-0.1%  [r_0603]
R114  5.76k-0.1%  [r_0603]
R117  1.5k-0.1%  [r_0603]
R118  680-0.1%  [r_0603]
R119  1k  [r_0603]
R120  1.07k-0.1%  [r_0603]
R121  910R-0.1%  [r_0603]
R122  5.76k-0.1%  [r_0603]
R123  1.5k-0.1%  [r_0603]
R124  680-0.1%  [r_0603]
R125  1k  [r_0603]
R126  1.07k-0.1%  [r_0603]
R127  910R-0.1%  [r_0603]
R128  5.76k-0.1%  [r_0603]
R129  1.5k-0.1%  [r_0603]
R130  680-0.1%  [r_0603]
R131  0  [r_0603]
R132  0  [r_0603]
R133  0  [r_0603]
R134  0  [r_0603]
R135  0  [r_0603]
R136  0  [r_0603]
TP23  TestPoint_Ring  [testpointD100]
TP24  TestPoint_Ring  [testpointD100]
TP25  TestPoint_Ring  [testpointD100]
TP26  TestPoint_Ring  [testpointD100]
TP42  TestPoint_Ring  [TestPointD100]
TP43  TestPoint_Ring  [TestPointD100]
TP44  TestPoint_Ring  [TestPointD100]
TP45  TestPoint_Ring  [TestPointD100]
TP46  TestPoint_Ring  [TestPointD100]
TP47  TestPoint_Ring  [TestPointD100]
TP63  TestPoint_Ring  [TestPointD100]
TP64  TestPoint_Ring  [TestPointD100]
TP65  TestPoint_Ring  [TestPointD100]
U19  STLM20W87F  [sot23-5p65_210x110l36x22n]
U27  TSV911IYLT  [sot23-5p95_280x145l45x40n]
U29  TLVH431AIL3T  [SOT23-3P97_255x140l40x40n]
U30  TSV911IYLT  [sot23-5p95_280x145l45x40n]
U31  TLVH431AIL3T  [SOT23-3P97_255x140l40x40n]
U32  TSV911IYLT  [sot23-5p95_280x145l45x40n]
U33  TLVH431AIL3T  [SOT23-3P97_255x140l40x40n]

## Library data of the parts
C1 C4 C6 C7 C9 = CAP_P: Cap Pol Radial (Electrolytic); 6.60 mm  X 6.60 mm X 5.50 mm H body; Any Equivalent?: YES; CLASS: DISCRETE; Dielectric Type: Capacitors; Manufacturer: WURTH; Manufacturer PN: 865230443004; PART_NUMBER: 865230443004; Package Size: Radial,6.6x5.5mm; Rated Voltage: *; STEP_MODEL: CAP_ALU_SMD-6x6H5.5
C2 C5 C10 = CAP: CAPACITOR CERAMIC SMD 0603; ALT_SYMBOLS: c_0603_hd; Any Equivalent?: YES; CLASS: DISCRETE; Dielectric Type: Capacitors; Manufacturer: WURTH; Manufacturer PN: 885012206075; PART_NUMBER: CAP-00000064; Package Size: 0603 (1608 Metric); Rated Voltage: *; Tolerance: *
C3 C8 C23 C25 C29 C30 C38 C40 C41 C43 C47 C49 C56 C58 C60 = CAP: CAPACITOR CERAMIC SMD 0603; ALT_SYMBOLS: c_0603_hd; Any Equivalent?: YES; CLASS: DISCRETE; Dielectric Type: Capacitors; Manufacturer: WURTH; Manufacturer PN: 885012206076; PART_NUMBER: CAP-00000064; Package Size: 0603 (1608 Metric); Rated Voltage: *; Tolerance: *
D1-D4 D7 = DIODE_LED: LED GREEN CLEAR 0805 SMD; Any Equivalent?: YES; CLASS: DISCRETE; Manufacturer: Wurth; Manufacturer PN: 150080YS75000; PART_NUMBER: TMP-1307; Package Size: 0805 (2012 Metric); Rated Current: 20mA
D5 D6 D8 = DIODE_LED: LED YELLOW CLEAR 0805 SMD; Any Equivalent?: YES; CLASS: DISCRETE; Manufacturer: Wurth; Manufacturer PN: 150080GS75000; PART_NUMBER: TMP-1306; Package Size: 0805 (2012 Metric); Rated Current: 20mA
F1-F16 = IND_FB: FERRITE BEAD 30 OHM 0805 1LN; Any Equivalent?: YES; CLASS: DISCRETE; Manufacturer: WURTH; Manufacturer PN: 742792030; PART_NUMBER: TMP-661; Package Size: 0805 (2012 Metric)
J1 J2 = CON3: SWITCH SLIDE SPDT 500MA 12V; Any Equivalent?: YES; CLASS: DISCRETE; Manufacturer: WURTH; Manufacturer PN: 450301014042; PART_NUMBER: TMP-679; Rated Current: 500mA (DC)
J47 J76 JP1 JP2 = CONN2: CONN TERM BLOCK 2POS 5.08MM PCB; Any Equivalent?: YES; CLASS: IO; Manufacturer: Wurth; Manufacturer PN: 691213510002; PART_NUMBER: 691213510002
R1-R7 R11 R13 R16 R34 R37 R39 = RES: CHIP RESISTOR SMD 1% 1/4W 1206; ALT_SYMBOLS: r_1206_hd; Any Equivalent?: YES; Manufacturer: ANY; Manufacturer PN: ANY; PART_NUMBER: Gen_R-000005; Package Size: 1206 (3216 Metric); Rated Power: 0.25W, 1/4W; STEP_MODEL: R_1206; Tolerance: 1%
TW1-TW19 = M_HOLE_NOT_PLATED: Mounting Hole M3 not plated - Pan Head; Any Equivalent?: NO; CLASS: Mechanical; PART_NUMBER: MIS-00000012
U1 = LD29080DTXX: IC REG LINEAR 5V 800MA DPAK; Any Equivalent?: NO; CLASS: IC; Manufacturer: STMicroelectronics; PART_NUMBER: IC-00000055; Package Size: TO-252-3, DPak (2 Leads + Tab), SC-63
U2 U3 = LD29080DTXX_1: IC REG LINEAR 3.3V 800MA SOT223; Any Equivalent?: NO; CLASS: IC; Manufacturer: STMicroelectronics; Manufacturer PN: LD29080S33R; More Info: To Provide; NOTE: To Provide; PART_NUMBER: TMP-681; Package Size: TO-261-4, TO-261AA
J3-J10 = JUMPER_3PIN: TIN DROP JUMPER  0603 3pin; CLASS: DISCRETE; PART_NUMBER: MIS-00000006; Package Size: 0603 (3pin drop)
P1 = CONN_ERNI32X2: Connector Erni 284166 32X2 female; Any Equivalent?: NO; CLASS: IO; Manufacturer: ERNI; Manufacturer PN: 284166; PART_NUMBER: CON-00000010
J11-J36 J50-J75 = CONN_TRBLK_1: Circuit Board Hardware - PCB RECPT. GOLD/NICKEL .106 IN. PRESSFIT; Any Equivalent?: NO; Manufacturer: Mill-Max
C11 C12 = FTDB_890744428006CS_30uF: Any Equivalent?: NO; Manufacturer: WURTH; Manufacturer PN: 890744428006CS; Rated Voltage: 1200
C14-C16 = FTDB_890764428004CS_75uF: Any Equivalent?: NO; Manufacturer: WURTH; Manufacturer PN: 890764428004CS; Rated Voltage: 600
C177-C182 C187 = CAP: CAPACITOR CERAMIC SMD 2220; ALT_SYMBOLS: c_2220_hd; Any Equivalent?: YES; CLASS: DISCRETE; Dielectric Type: Capacitors; Manufacturer: WURTH; Manufacturer PN: 885342214001; PART_NUMBER: CAP-00000064; Package Size: 2220; Rated Voltage: *; Tolerance: *
C183-C186 = CAP: CAPACITOR CERAMIC SMD 2220; ALT_SYMBOLS: c_2220_hd; Any Equivalent?: YES; CLASS: DISCRETE; Dielectric Type: Capacitors; Manufacturer: WURTH; Manufacturer PN: 885342214173; PART_NUMBER: CAP-00000064; Package Size: 2220; Rated Voltage: *; Tolerance: *
J37-J42 J45 J46 = CON-ERNI-2147xx_2: Power to the Board 10MM 40A SOLDER SCREW M4; Any Equivalent?: NO; CLASS: IO; Manufacturer: WURTH
T1 = COILCRAFT_CST3015: Tranf,Radio 1:100,80A; Any Equivalent?: NO; CLASS: DISCRETE; Manufacturer: Coilcraft; Manufacturer PN: CST3015-100E; PART_NUMBER: XFMR-00000023; Package Size: 30x23mm
T2 = Frenetic_32011-04: Any Equivalent?: NO; CLASS: DISCRETE; PART_NUMBER: TMP-2129
TP27-TP34 = TEST_POINT
TP48-TP62 TP66-TP75 = TESTPOINT: PC TEST POINT NATURAL; Any Equivalent?: NO; CLASS: IO; Manufacturer: Harwin Inc.; Manufacturer PN: S1751-46R; PART_NUMBER: CON-00000231; Package Size: 0.128" L x 0.065" W (3.25mm x 1.65mm)
U4 = A2F12M12W2-F1: ACEPACK™ 2 – Full-bridge - 1200V, 12mO SiC; Any Equivalent?: NO; CLASS: DISCRETE; Manufacturer: STMicroelectronics; PART_NUMBER: XSTR-00000008; Rated Voltage: 1200V
U5 U6 = A2H6M12W2: ACEPACK™ 2 - Half-bridge - 1200V, 6mO SiC MOSFET Gen2 and NTC; Any Equivalent?: NO; CLASS: DISCRETE; Manufacturer: STSTMicroelectronics; PART_NUMBER: XSTR-00000042; Rated Voltage: 1200V
W35-W42 W45-W48 W50 W53-W55 = CON-ERNI-2147xx_0: Any Equivalent?: NO; CLASS: IO; Manufacturer: ANY
W43 W56-W62 = CON-ERNI-2147xx_0: HEX STANDOFF M3X0.5 STEEL 50MM; Any Equivalent?: NO; CLASS: IO; Manufacturer: WURTH; Manufacturer PN: 971500321
C24 C26 C28 C31 C32 C39 C42 C44 C46 C50 C52 C57 C59 C66-C68 = CAP: CAPACITOR CERAMIC SMD 0603; ALT_SYMBOLS: c_0603_hd; Any Equivalent?: YES; CLASS: DISCRETE; Dielectric Type: Capacitors; Manufacturer: WURTH; Manufacturer PN: 885012206071; PART_NUMBER: CAP-00000064; Package Size: 0603 (1608 Metric); Rated Voltage: *; Tolerance: *
C27 C34 C35 C37 C45 C48 C53 C55 C61-C65 C76 = CAP: CAPACITOR CERAMIC SMD 0603; ALT_SYMBOLS: c_0603_hd; Any Equivalent?: YES; CLASS: DISCRETE; Dielectric Type: Capacitors; Manufacturer: ANY; Manufacturer PN: ANY; PART_NUMBER: CAP-00000064; Package Size: 0603 (1608 Metric); Rated Voltage: *; Tolerance: *
C33 C51 = CAP: CAPACITOR CERAMIC SMD 0603; ALT_SYMBOLS: c_0603_hd; Any Equivalent?: YES; CLASS: DISCRETE; Dielectric Type: Capacitors; Manufacturer: WURTH; Manufacturer PN: 885012106012; PART_NUMBER: CAP-00000064; Package Size: 0603 (1608 Metric); Rated Voltage: *; Tolerance: *
C36 C54 = CAP: CAPACITOR CERAMIC SMD 0603; ALT_SYMBOLS: c_0603_hd; Any Equivalent?: YES; CLASS: DISCRETE; Dielectric Type: Capacitors; Manufacturer: WURTH; Manufacturer PN: 885012006029; PART_NUMBER: CAP-00000064; Package Size: 0603 (1608 Metric); Rated Voltage: *; Tolerance: *
LEM1 LEM2 = LTSR15-NP_0: SENSOR CURRENT HALL 15A AC/DC; Any Equivalent?: NO; CLASS: DISCRETE; Manufacturer: LEM USA Inc.; Package Size: Ring Opening 0.126" Dia, 6 Leads
R8-R10 R12 R14 R15 R17-R33 R35 R36 R38 R40-R64 = RES: CHIP RESISTOR SMD 1% 1/10W 0603; ALT_SYMBOLS: r_0603_hd; Any Equivalent?: YES; Manufacturer: ANY; Manufacturer PN: ANY; PART_NUMBER: Gen_R-000003; Package Size: 0603 (1608 Metric); Rated Power: 0.1W, 1/10W; Tolerance: 1%
R66 = RES: CHIP RESISTOR SMD 2512; Any Equivalent?: YES; Manufacturer: ANY; Manufacturer PN: ANY; PART_NUMBER: Gen_R-000008; Package Size: 2512 (6332 metric)
TP1-TP26 = TestPoint_Ring_0: TestPoint RIng; Any Equivalent?: YES
U7 U12 = TSV911ILT: IC OPAMP GP 8MHZ RRO SOT23-5; ALT_SYMBOLS: sot23-5p95_280x145l45x40l; Any Equivalent?: NO; CLASS: IC; Manufacturer: STMicroelectronics; PART_NUMBER: TMP-861; Package Size: SC-74A, SOT-753, SOT23-5L; Supply Voltage: 2.5 V ~ 5.5 V
U8 U14 = AMC1311QDWVRQ1: IC ISOLATION 8SOIC; Any Equivalent?: NO; CLASS: IC; Manufacturer: Texas Instruments; PART_NUMBER: IC-00000157; Package Size: 8-SOIC (0.295", 7.50mm Width)
U9 U15 U17 = TSV912IDT: IC OPAMP GP 8MHZ RRO 8SO; Any Equivalent?: NO; CLASS: IC; Manufacturer: STMicroelectronics; PART_NUMBER: IC-00000061; Package Size: 8-SOIC (0.154", 3.90mm Width); Supply Voltage: 2.5 V ~ 5.5 V
U10 U13 U18 U29 U31 U33 = TL431: IC VREF SHUNT ADJ SOT23-3; Any Equivalent?: NO; CLASS: IC; Manufacturer: STMicroelectronics; PART_NUMBER: IC-00000081; Package Size: TO-236-3, SC-59, SOT-23-3
U11 U20 = DCH0105: DC DC CONVERTER 5V 1W; Any Equivalent?: NO; CLASS: IC; Manufacturer: WURTH; Package Size: 7-SIP Module, 4 Leads; Rated Power: 1W
C171 C173 C175 = CAP: CAPACITOR CERAMIC SMD 0603; ALT_SYMBOLS: c_0603_hd; Any Equivalent?: no; CLASS: DISCRETE; Dielectric Type: Capacitors; Manufacturer: Würth Elektronik; Manufacturer PN: 885012206071R; PART_NUMBER: 885012206071R; Package Size: 0603 (1608 Metric); Rated Voltage: 25; Tolerance: 10
C172 C174 C176 = CAP: CAPACITOR CERAMIC SMD 0603; ALT_SYMBOLS: c_0603_hd; Any Equivalent?: no; CLASS: DISCRETE; Dielectric Type: Capacitors; Manufacturer: Würth Elektronik; Manufacturer PN: 885012206076; PART_NUMBER: 885012206076; Package Size: 0603 (1608 Metric); Rated Voltage: 25; Tolerance: 10
FAN1-FAN6 = 109P0412G3013: Sanyo Denki 109P Series Axial Fan, 12 V dc, DC Operation, 25.1m³/h, 3.72W, 40 x 40 x 28mm; Any Equivalent?: NO; Manufacturer: Sanyo Denki
HS1 = SK_56_100_AL: SK 56 100 AL | FISCHER ELEKTRONIK; Any Equivalent?: NO; Manufacturer: fischerelektronik; Manufacturer PN: SK 56 100 AL
L30-L32 = 742792021-FB: Manufacturer: Würth Elektronik; Manufacturer PN: 742792021; PART_NUMBER: 742792021; Package Size: 0805; Rated Current: 6A
LOGO1 = LOGO_ST: ST LOGO - SILKSCREEN; ALT_SYMBOLS: stlogo11mm,STLogo10mm,STLogo9mm,STLogo8mm,STLogo7mm,STLogo6mm,STLogo5mm,stlogo4mm; CLASS: Mechanical; PART_NUMBER: MECH-00000001
LOGO2 = LOGO_HOT_SURFACE: HOT SURFACE LOGO - SILKSCREEN; ALT_SYMBOLS: Hot-Surface-Logo10mm,Hot-Surface-Logo12mm; Any Equivalent?: NO; CLASS: Mechanical; PART_NUMBER: MIS-00000011
Q1 = STS6NF20V: MOSFET N-CH 20V 6A 8SOIC; Any Equivalent?: NO; CLASS: DISCRETE; Manufacturer: STMicroelectronics; More Info: To Provide; NOTE: To Provide; PART_NUMBER: TMP-561; Package Size: 8-SOIC (0.154", 3.90mm Width); Polarity: N-Channel
R108 R110 R114 R119 R120 R122 R125 R126 R128 = RES: CHIP RESISTOR SMD 1% 1/10W 0603; ALT_SYMBOLS: r_0603_hd; Any Equivalent?: YES; PART_NUMBER: Gen_R-000003; Package Size: 0603 (1608 Metric); Rated Power: 0.1W, 1/10W; Tolerance: 1%
R111 R117 R118 R121 R123 R124 R127 R129-R136 = RES: CHIP RESISTOR SMD 0.1% 1/10W 0603; ALT_SYMBOLS: r_0603_hd; Any Equivalent?: YES; PART_NUMBER: Gen_R-000003; Package Size: 0603 (1608 Metric); Rated Power: 0.1W, 1/10W; Tolerance: 0.1%
TP42-TP47 TP63-TP65 = TestPoint_Ring_0
U19 = STLM20W87F: SENS TEMP ANLG VOLT SOT-323-5; Any Equivalent?: NO; CLASS: IC; More Info: To Provide; NOTE: To Provide; PART_NUMBER: TMP-660; Package Size: 5-TSSOP, SC-70-5, SOT-353; Supply Voltage: 2.7 V ~ 5.5 V
U27 U30 U32 = TSV911ILT: IC OPAMP GP 8MHZ RRO SOT23-5; ALT_SYMBOLS: sot23-5p95_280x145l45x40l; CLASS: IC; Manufacturer: STMicroelectronics; PART_NUMBER: TMP-861; Package Size: SC-74A, SOT-753, SOT23-5L; Supply Voltage: 2.5 V ~ 5.5 V

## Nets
5V_DC1: C40.1 F6.1 U11.7(+V0)
5V_DC2: C60.1 F14.1 U20.7(+V0)
GND: C1.2 C2.2 C3.2 C4.2 C5.2 C6.2 C7.2 C8.2 C9.2 C10.2 C23.2 C24.2 C25.2 C26.2 C27.2 C28.2 C29.2 C32.2 C33.2 C34.2 C37.2 C38.2 C39.2 C41.2 C42.2 C43.2 C44.2 C45.2 C46.2 C47.2 C48.2 C51.2 C52.2 C55.2 C56.2 C57.2 C58.2 C59.2 C62.1 C63.2 C64.1 C66.2 C67.1 C68.2 C171.2 C172.2 C173.2 C174.2 C175.2 C176.2 D1.C D2.C D3.C D4.C D5.C D6.C D7.C J3.1 J4.1 J5.1 J6.1 J7.1 J8.1 J9.1 J10.1 J58.1 J59.1 J72.1 J73.1 J74.1 J75.1 J76.2 JP1.2 JP2.2 LEM1.13(GND) LEM2.13(GND) P1.16B P1.21B P1.22B P1.23B P1.24B P1.25B P1.26B P1.27B P1.28B P1.29B P1.30B P1.31B P1.32B Q1.1(Source2) Q1.2(Source1) Q1.3(Source) R8.2 R9.2 R17.1 R23.1 R28.2 R29.2 R38.1 R40.2 R55.1 R63.1 R64.1 R111.1 R114.1 R121.1 R122.1 R127.1 R128.1 TP4.1 TP7.1 TP14.1 TP15.1 TP24.1 TP26.1 TP63.1 TP64.1 TP65.1 U1.4(GND) U2.1(GND) U3.1(GND) U7.2(V-) U8.5(GND2) U9.4(V-) U10.3(A) U11.2(-VIN) U12.2(V-) U13.3(A) U14.5(GND2) U15.4(V-) U17.4(V-) U18.3(A) U19.5(GND1) U20.2(-VIN) U27.2(V-) U29.3(A) U30.2(V-) U31.3(A) U32.2(V-) U33.3(A)
GND_DX_HS_1: J5.2 J55.1
GND_DX_HS_2: J9.2 J69.1
GND_DX_LS_1: J6.2 J57.1
GND_DX_LS_2: J10.2 J71.1
GND_MEAS_DC: C49.2 C50.2
GND_SX_HS_1: J3.2 J54.1
GND_SX_HS_2: J7.2 J68.1
GND_SX_LS_1: J4.2 J56.1
GND_SX_LS_2: J8.2 J70.1
VDD_3.3V: C4.1 P1.7B R4.1 U2.2(VOUT) U2.4(VOUT1)
VDD_3.3V_DRIVER: C9.1 J31.1 J32.1 J33.1 R5.1 U3.2(VOUT) U3.4(VOUT1)
VDD_5V: C6.1 C67.2 F2.2 F4.1 F5.2 F7.1 F8.1 F9.1 F10.1 F11.2 F12.1 F13.1 F15.1 F16.1 L30.2 L31.2 L32.2 P1.7A R3.1 R14.1 R32.1 R49.1 R108.1 R119.1 R125.1 R131.1 R134.1 R135.1 U1.3(VOUT) U19.4(VCC)
VDD_7V: F1.2 J1.2 R2.1
VDD_7V_EXT: C1.1 C3.1 J1.3 JP1.1 R1.1
VDD_12V: F3.2 J2.2 J34.1 J35.1 J36.1 R7.1
VDD_12V_EXT: C7.1 C8.1 J2.3 JP2.1 R6.1
VDD_ref_NTC_HV: R108.2 R110.2 R117.2 TP42.1 U29.1(K)
VDD_ref_NTC_LV1: R125.2 R126.2 R129.2 TP46.1 U33.1(K)
VDD_ref_NTC_LV2: R119.2 R120.2 R123.2 TP44.1 U31.1(K)
BUS_LEM_DC1+: J39.1 J39.2 J39.3 J39.4 J39.5 J39.6 J39.7 J39.8 J39.9 LEM1.1(IN-1) LEM1.2(IN-2) LEM1.3(IN-3) TP70.1
BUS_LEM_DC1-: C11.1 C11.2(4) C12.1 C12.2(4) C183.1 C184.1 C185.1 C186.1 LEM1.8(OUT-1) LEM1.9(OUT-2) LEM1.10(OUT-3) R11.1 TP28.1 TP52.1 U4.P1 U4.P2 U4.P3 U4.P4 U4.P5 U4.P6 U4.P7 U4.P8
BUS_LEM_DC2+: C14.1 C14.2(4) C15.1 C15.2(4) C16.1 C16.2(4) C177.1 C178.1 C179.1 C180.1 C181.1 C182.1 C187.1 LEM2.1(IN-1) LEM2.2(IN-2) LEM2.3(IN-3) R34.1 TP32.1 TP55.1 TP56.1 TP74.1 TP75.1 U5.P_1 U5.P_2 U5.P_3 U5.P_4 U5.P_5 U5.P_6 U5.P_7 U5.P_8 U6.P_1 U6.P_2 U6.P_3 U6.P_4 U6.P_5 U6.P_6 U6.P_7 U6.P_8
BUS_LEM_DC2-: J40.1 J40.2 J40.3 J40.4 J40.5 J40.6 J40.7 J40.8 J40.9 LEM2.8(OUT-1) LEM2.9(OUT-2) LEM2.10(OUT-3) TP72.1
FAN: P1.15A R62.2 TP23.1
G_DX_HS_1: J18.1 U4.G3
G_DX_HS_2A: J12.1 U6.GH_1
G_DX_HS_2B: J14.1 U6.GH_2
G_DX_LS_1: J22.1 U4.G4
G_DX_LS_2A: J16.1 U6.GL_1
G_DX_LS_2B: J20.1 U6.GL_2
G_SX_HS_1: J17.1 U4.G1
G_SX_HS_2A: J11.1 U5.GH_1
G_SX_HS_2B: J13.1 U5.GH_2
G_SX_LS_1: J21.1 U4.G2
G_SX_LS_2A: J15.1 U5.GL_1
G_SX_LS_2B: J19.1 U5.GL_2
I_CT+: C76.2 R48.1 R66.1 T1.4 TP20.1
I_CT-: C76.1 R58.2 R66.2 T1.3 TP19.1
I_CT_adc: C64.2 P1.22A P1.24A P1.30A R53.1 TP21.1
Idc1_LEM: C27.1 P1.20A R12.2 TP3.1
Idc2_LEM: C45.1 P1.21A R31.2 TP12.1
NTC_HV+: R131.2 U4.T1
NTC_HV-: R132.2 U4.T2
NTC_HV_Temp: P1.27A R118.2 TP43.1 U27.1(OUT)
NTC_LV1+: R135.2 U5.T1
NTC_LV1-: R136.2 U5.T2
NTC_LV1_Temp: P1.25A R130.2 TP47.1 U32.1(OUT)
NTC_LV2+: R134.2 U6.T1
NTC_LV2-: R133.2 U6.T2
NTC_LV2_Temp: P1.26A R124.2 TP45.1 U30.1(OUT)
OUTA_DAB1: J37.1 J37.2 J37.3 J37.4 J37.5 J37.6 J37.7 J37.8 J37.9 TP29.1 TP50.1 TP66.1 U4.OUT1A U4.OUT1B U4.OUT1C U4.OUT1D
OUTA_DAB2: J38.1 J38.2 J38.3 J38.4 J38.5 J38.6 J38.7 J38.8 J38.9 TP33.1 TP57.1 TP58.1 TP67.1 U5.OUT_1 U5.OUT_2 U5.OUT_3 U5.OUT_4 U5.OUT_5 U5.OUT_6 U5.OUT_7 U5.OUT_8 U5.OUT_9 U5.OUT_10
OUTB_DAB1: T1.2 TP30.1 TP51.1 U4.OUT2A U4.OUT2B U4.OUT2C U4.OUT2D
OUTB_DAB2: J42.1 J42.2 J42.3 J42.4 J42.5 J42.6 J42.7 J42.8 J42.9 TP34.1 TP59.1 TP60.1 TP68.1 U6.OUT_1 U6.OUT_2 U6.OUT_3 U6.OUT_4 U6.OUT_5 U6.OUT_6 U6.OUT_7 U6.OUT_8 U6.OUT_9 U6.OUT_10
POWER_N_1: C11.3 C11.4(2) C12.3 C12.4(2) C30.2 C31.2 C36.2 C40.2 C183.2 C184.2 C185.2 C186.2 J45.1 J45.2 J45.3 J45.4 J45.5 J45.6 J45.7 J45.8 J45.9 R24.1 TP5.1 TP27.1 TP48.1 TP49.1 TP71.1 U4.N2A U4.N2B U4.N2C U4.N2D U4.N4A U4.N4B U4.N4C U4.N4D U8.3(SHTDN) U8.4(GND1) U11.5(-VO)
POWER_N_2: C14.3 C14.4(2) C15.3 C15.4(2) C16.3 C16.4(2) C54.2 C60.2 C177.2 C178.2 C179.2 C180.2 C181.2 C182.2 C187.2 J46.1 J46.2 J46.3 J46.4 J46.5 J46.6 J46.7 J46.8 J46.9 R44.2 TP16.1 TP31.1 TP53.1 TP54.1 TP61.1 TP62.1 TP73.1 U5.N_1 U5.N_2 U5.N_3 U5.N_4 U5.N_5 U5.N_6 U5.N_7 U5.N_8 U6.N_1 U6.N_2 U6.N_3 U6.N_4 U6.N_5 U6.N_6 U6.N_7 U6.N_8 U14.3(SHTDN) U14.4(GND1) U20.5(-VO)
PWM_DX_HS_1: J6.3 J26.1 P1.12A
PWM_DX_HS_2: J10.3 J24.1 P1.10B
PWM_DX_LS_1: J5.3 J30.1 P1.11A
PWM_DX_LS_2: J9.3 J28.1 P1.9B
PWM_SX_HS_1: J4.3 J25.1 P1.10A
PWM_SX_HS_2: J8.3 J23.1 P1.14A
PWM_SX_LS_1: J3.3 J29.1 P1.9A
PWM_SX_LS_2: J7.3 J27.1 P1.13A
S_DX_HS_1: J51.1 U4.S3
S_DX_HS_2A: J61.1 U6.SH_1
S_DX_HS_2B: J63.1 U6.SH_2
S_DX_LS_1: J53.1 U4.S4
S_DX_LS_2A: J65.1 U6.SL_1
S_DX_LS_2B: J67.1 U6.SL_2
S_SX_HS_1: J50.1 U4.S1
S_SX_HS_2A: J60.1 U5.SH_1
S_SX_HS_2B: J62.1 U5.SH_2
S_SX_LS_1: J52.1 U4.S2
S_SX_LS_2A: J64.1 U5.SL_1
S_SX_LS_2B: J66.1 U5.SL_2
TEMP: C68.1 P1.29A R61.1 R63.2 TP25.1
V_bus_DC1: P1.31A TP9.1 U9.6(-) U9.7(OUT)
V_bus_DC2: P1.32A TP18.1 U15.6(-) U15.7(OUT)
N16831100: R11.2 R13.1
N16831102: C30.1 C31.1 F6.2 U8.1(VDD1)
N16831112: C32.1 C33.1 F7.2 U8.8(VDD2)
N16831136: C28.1 C29.1 F8.2 U9.8(V+)
N16831308: C35.1 R17.2 R21.2 U9.3(+)
N16831320: R20.1 U8.7(VOUTP)
N16831355: R25.1 U8.6(VOUTN)
N16831361: R20.2 R21.1
N16831402: R22.1 R27.2 U9.1(OUT)
N16831410: C37.1 R22.2 U9.5(+)
N16831500: R25.2 R26.1
N16831508: C35.2 R26.2 R27.1 U9.2(-)
N16833350: J47.1 J76.1 R60.2
N16833352: R59.2 R61.2 U19.3(VOUT)
N16833356: C66.1 R59.1
N16833384: D8.A R60.1
N16833392: D8.C J47.2 Q1.5(D5) Q1.6(D6) Q1.7(D7) Q1.8(D8)
N16833559: Q1.4(Gate) R62.1 R64.2
N16835059: C10.1 F3.1 U3.3(VIN)
N16835108: C5.1 F1.1 U1.1(VIN)
N16835390: D3.A R3.2
N16835406: D4.A R4.2
N16835530: D2.A R2.2
N16837926: C36.1 R16.2 R24.2 TP8.1 U8.2(VIN)
N16840573: R34.2 R37.1
N16840575: C49.1 C50.1 F14.2 U14.1(VDD1)
N16840585: C51.1 C52.1 F13.2 U14.8(VDD2)
N16840661: C46.1 C47.1 F12.2 U15.8(V+)
N16840835: C54.1 R39.2 R44.1 TP17.1 U14.2(VIN)
N16840895: R41.1 U14.7(VOUTP)
N16840899: R41.2 R42.1
N16840903: C53.1 R40.1 R42.2 U15.3(+)
N16840932: R45.1 U14.6(VOUTN)
N16841001: R43.1 R47.2 U15.1(OUT)
N16841011: C55.1 R43.2 U15.5(+)
N16841045: C53.2 R46.2 R47.1 U15.2(-)
N16841135: R45.2 R46.1
N16846096: C38.1 C39.1 F9.2 U11.1(+VIN)
N16879516: C58.1 C59.1 F16.2 U20.1(+VIN)
N16880580: C23.1 C24.1 F4.2 U7.5(V+)
N16880586: C25.1 C26.1 F5.1 LEM1.14(Vc)
N16880592: LEM1.11(Ref) R8.1
N16880630: LEM1.12(OUT) R10.1 TP1.1
N16880681: R9.1 R10.2 U7.3(+IN)
N16880750: R12.1 R19.2 TP2.1 U7.1(OUT)
N16880858: R15.2 R19.1 U7.4(-IN)
N16883264: C34.1 R14.2 R15.1 R18.2 TP6.1 U10.1(K)
N16889161: R18.1 R23.2 U10.2(REF)
N16893320: C41.1 C42.1 F10.2 U12.5(V+)
N16893396: C43.1 C44.1 F11.1 LEM2.14(Vc)
N16893406: LEM2.11(Ref) R28.1
N16893433: LEM2.12(OUT) R30.1 TP10.1
N16893485: R29.1 R30.2 U12.3(+IN)
N16893526: R31.1 R36.2 TP11.1 U12.1(OUT)
N16893565: R33.2 R36.1 U12.4(-IN)
N16893634: C48.1 R32.2 R33.1 R35.2 TP13.1 U13.1(K)
N16893709: R35.1 R38.2 U13.2(REF)
N16906968: C65.1 R56.2 R58.1 U17.2(-)
N16907757: C56.1 C57.1 F15.2 U17.8(V+)
N16909345: C65.2 R51.2 R56.1 U17.1(OUT)
N16909762: R48.2 R50.1 U17.3(+)
N16909888: C63.1 R49.2 R50.2 R54.2 TP22.1 U18.1(K)
N16909939: R54.1 R55.2 U18.2(REF)
N16910733: C62.2 R52.1 U17.5(+)
N16910739: C61.2 R51.1 R52.2
N16911855: R57.2 U17.6(-)
N16911860: C61.1 R53.2 R57.1 U17.7(OUT)
N16989795: D7.A R5.2
N17019395: C2.1 F2.1 U2.3(VIN)
N17031429: J41.1 J41.2 J41.3 J41.4 J41.5 J41.6 J41.7 J41.8 J41.9 T1.1 TP69.1
N17069289: C171.1 C172.1 L30.1 U27.5(V+)
N17069365: R111.2 R132.1 U27.3(+IN)
N17069399: R117.1 R118.1 U27.4(-IN)
N17069424: R110.1 R114.2 U29.2(REF)
N17069702: C173.1 C174.1 L31.1 U30.5(V+)
N17069778: R121.2 R133.1 U30.3(+IN)
N17069812: R123.1 R124.1 U30.4(-IN)
N17069837: R120.1 R122.2 U31.2(REF)
N17070028: C175.1 C176.1 L32.1 U32.5(V+)
N17070104: R127.2 R136.1 U32.3(+IN)
N17070138: R129.1 R130.1 U32.4(-IN)
N17070163: R126.1 R128.2 U33.2(REF)
N17115138: R13.2 R16.1
N17115188: R37.2 R39.1
N17124173: D5.A R6.2
N17124313: D6.A R7.2
N17124652: D1.A R1.2

Not connected (* = marked no-connect by the designer): J1 1; J2 1; P1 1A* 1B* 2A* 2B* 3A 3B 4A* 4B* 5A* 5B* 6A* 6B* 8A* 8B* 11B* 12B* 13B* 14B* 15B* 16A* 17A* 17B* 18A* 18B* 19A* 19B* 20B* 23A* 28A; T2 1* 2* A* B* C* D*; U19 1(NC)* 2(GND)
